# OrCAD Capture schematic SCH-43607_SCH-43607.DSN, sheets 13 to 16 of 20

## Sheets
13 P13_CPU SERDES & CLOCKS: size C
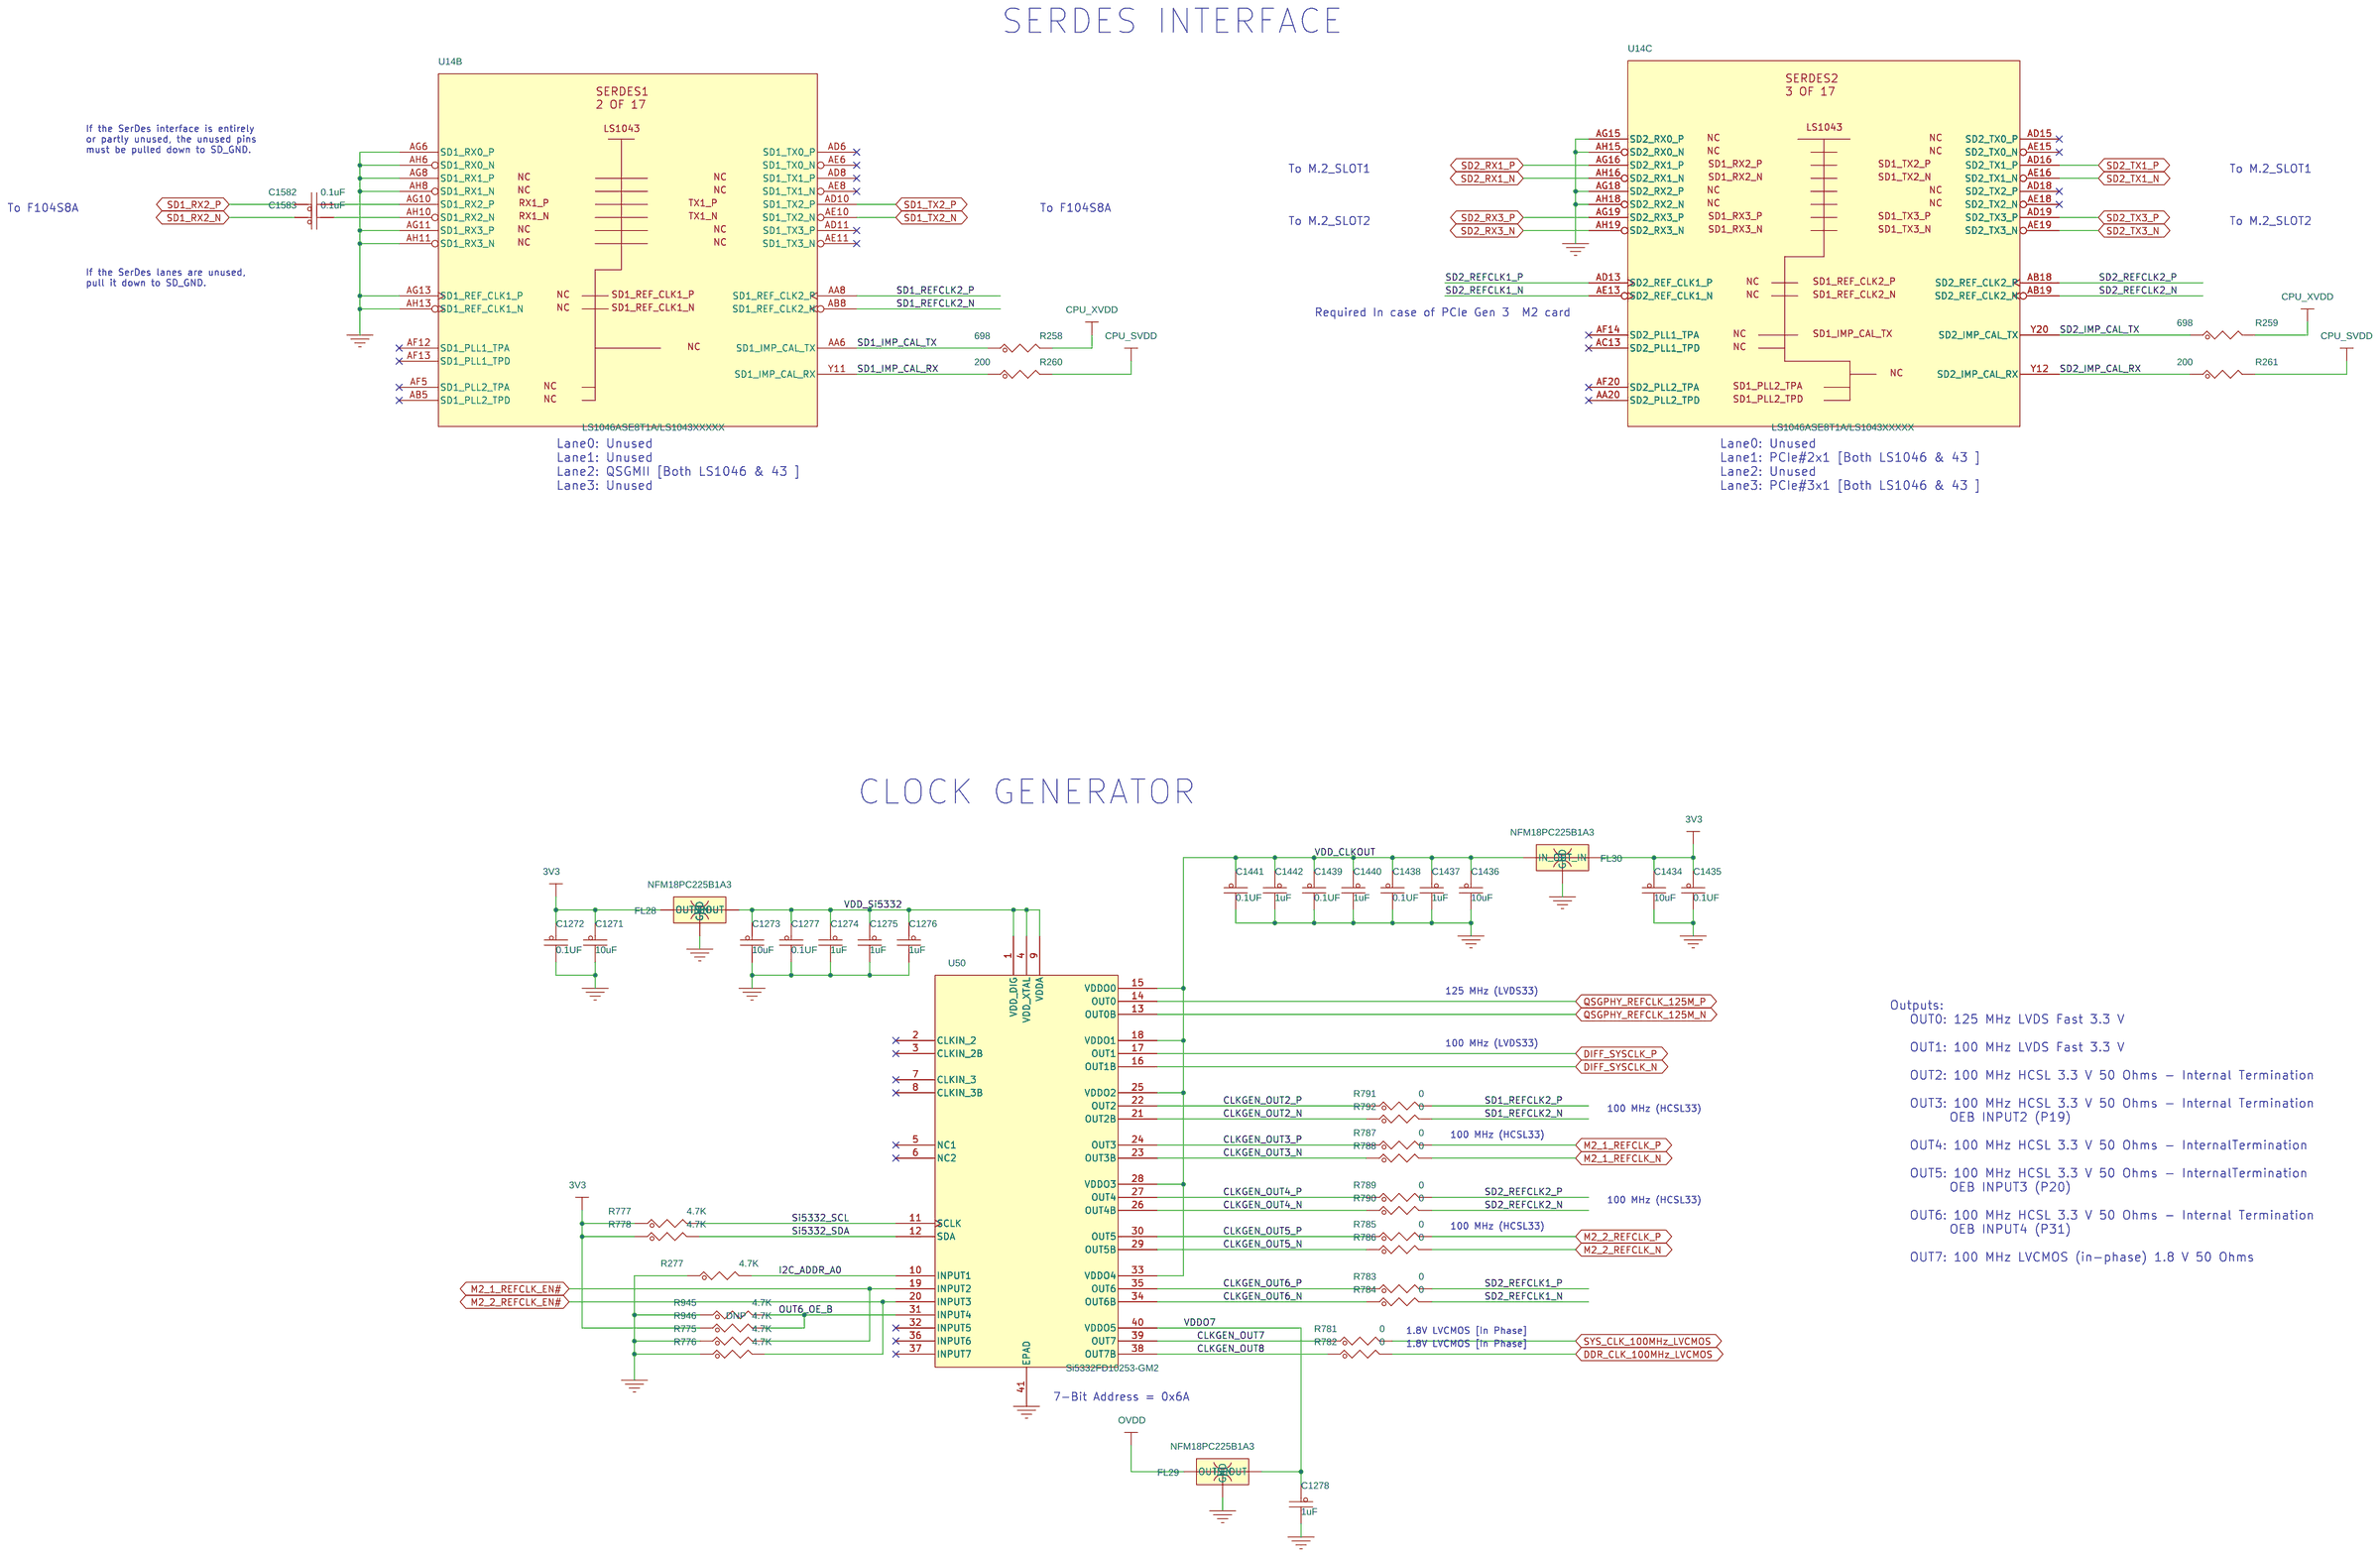
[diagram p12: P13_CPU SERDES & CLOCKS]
14 P14_M.2_PCIe_CARD: size C
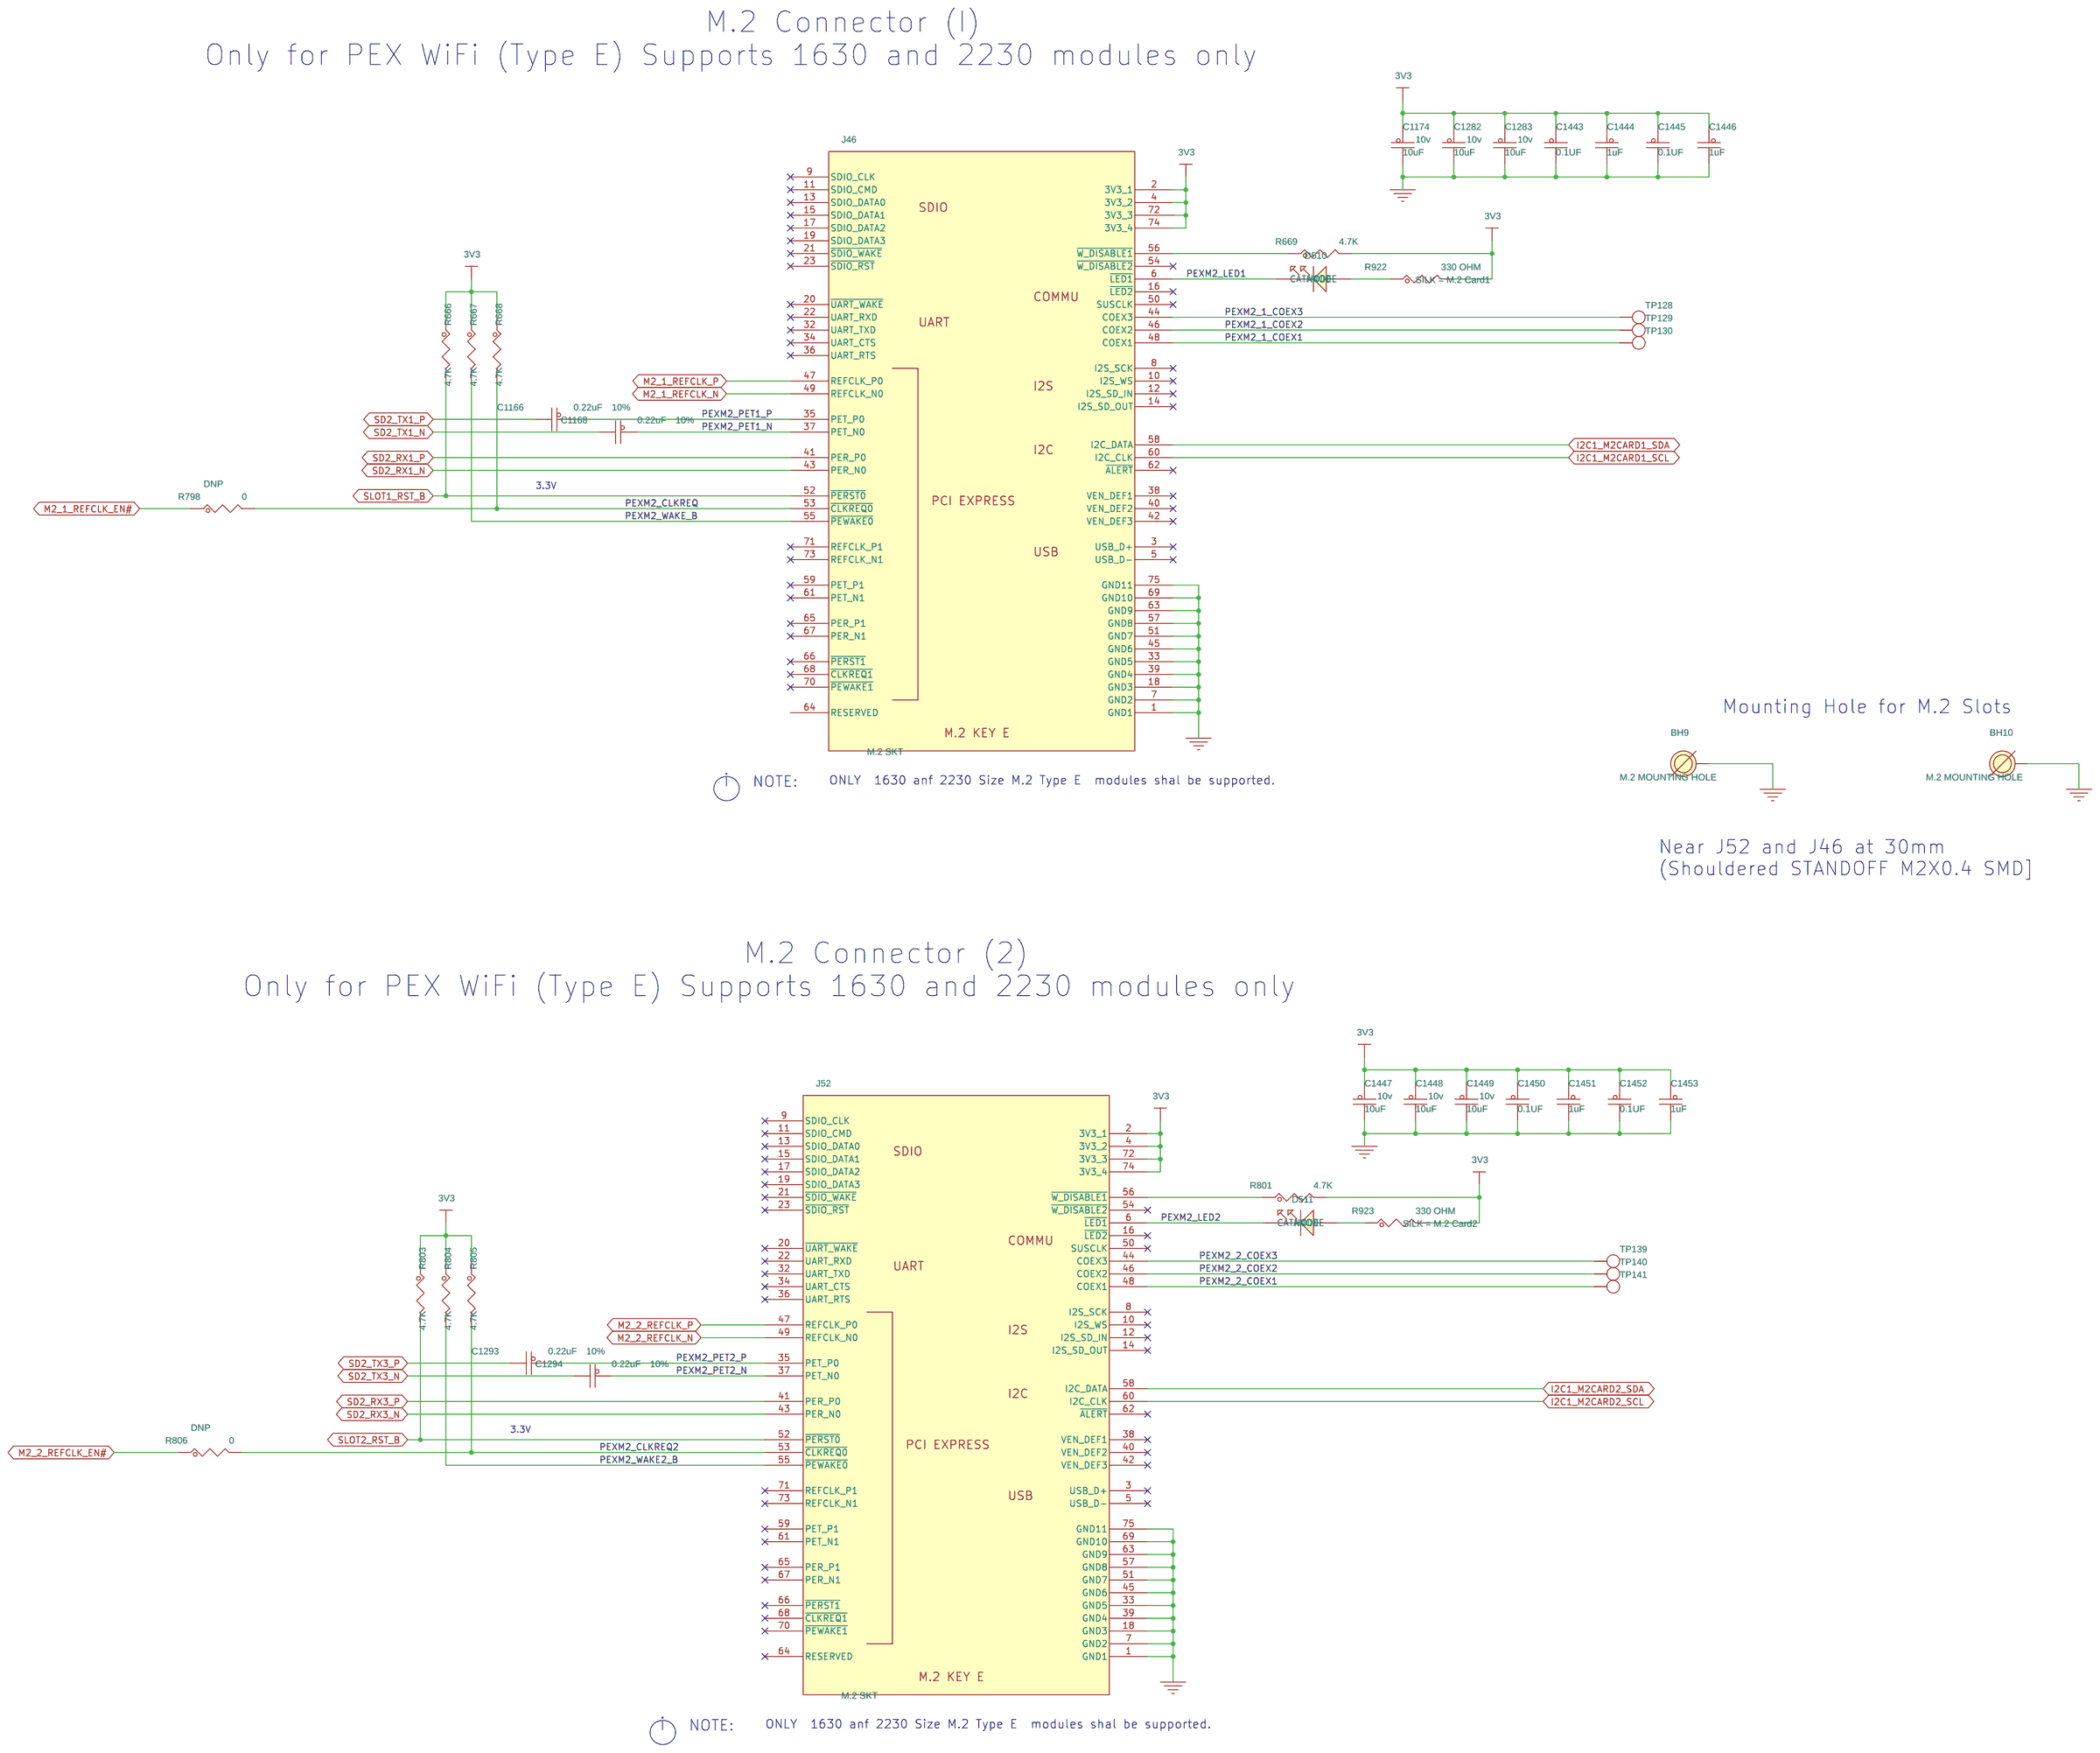
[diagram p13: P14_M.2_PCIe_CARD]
15 P15_QSGMII PHY (F104): size C
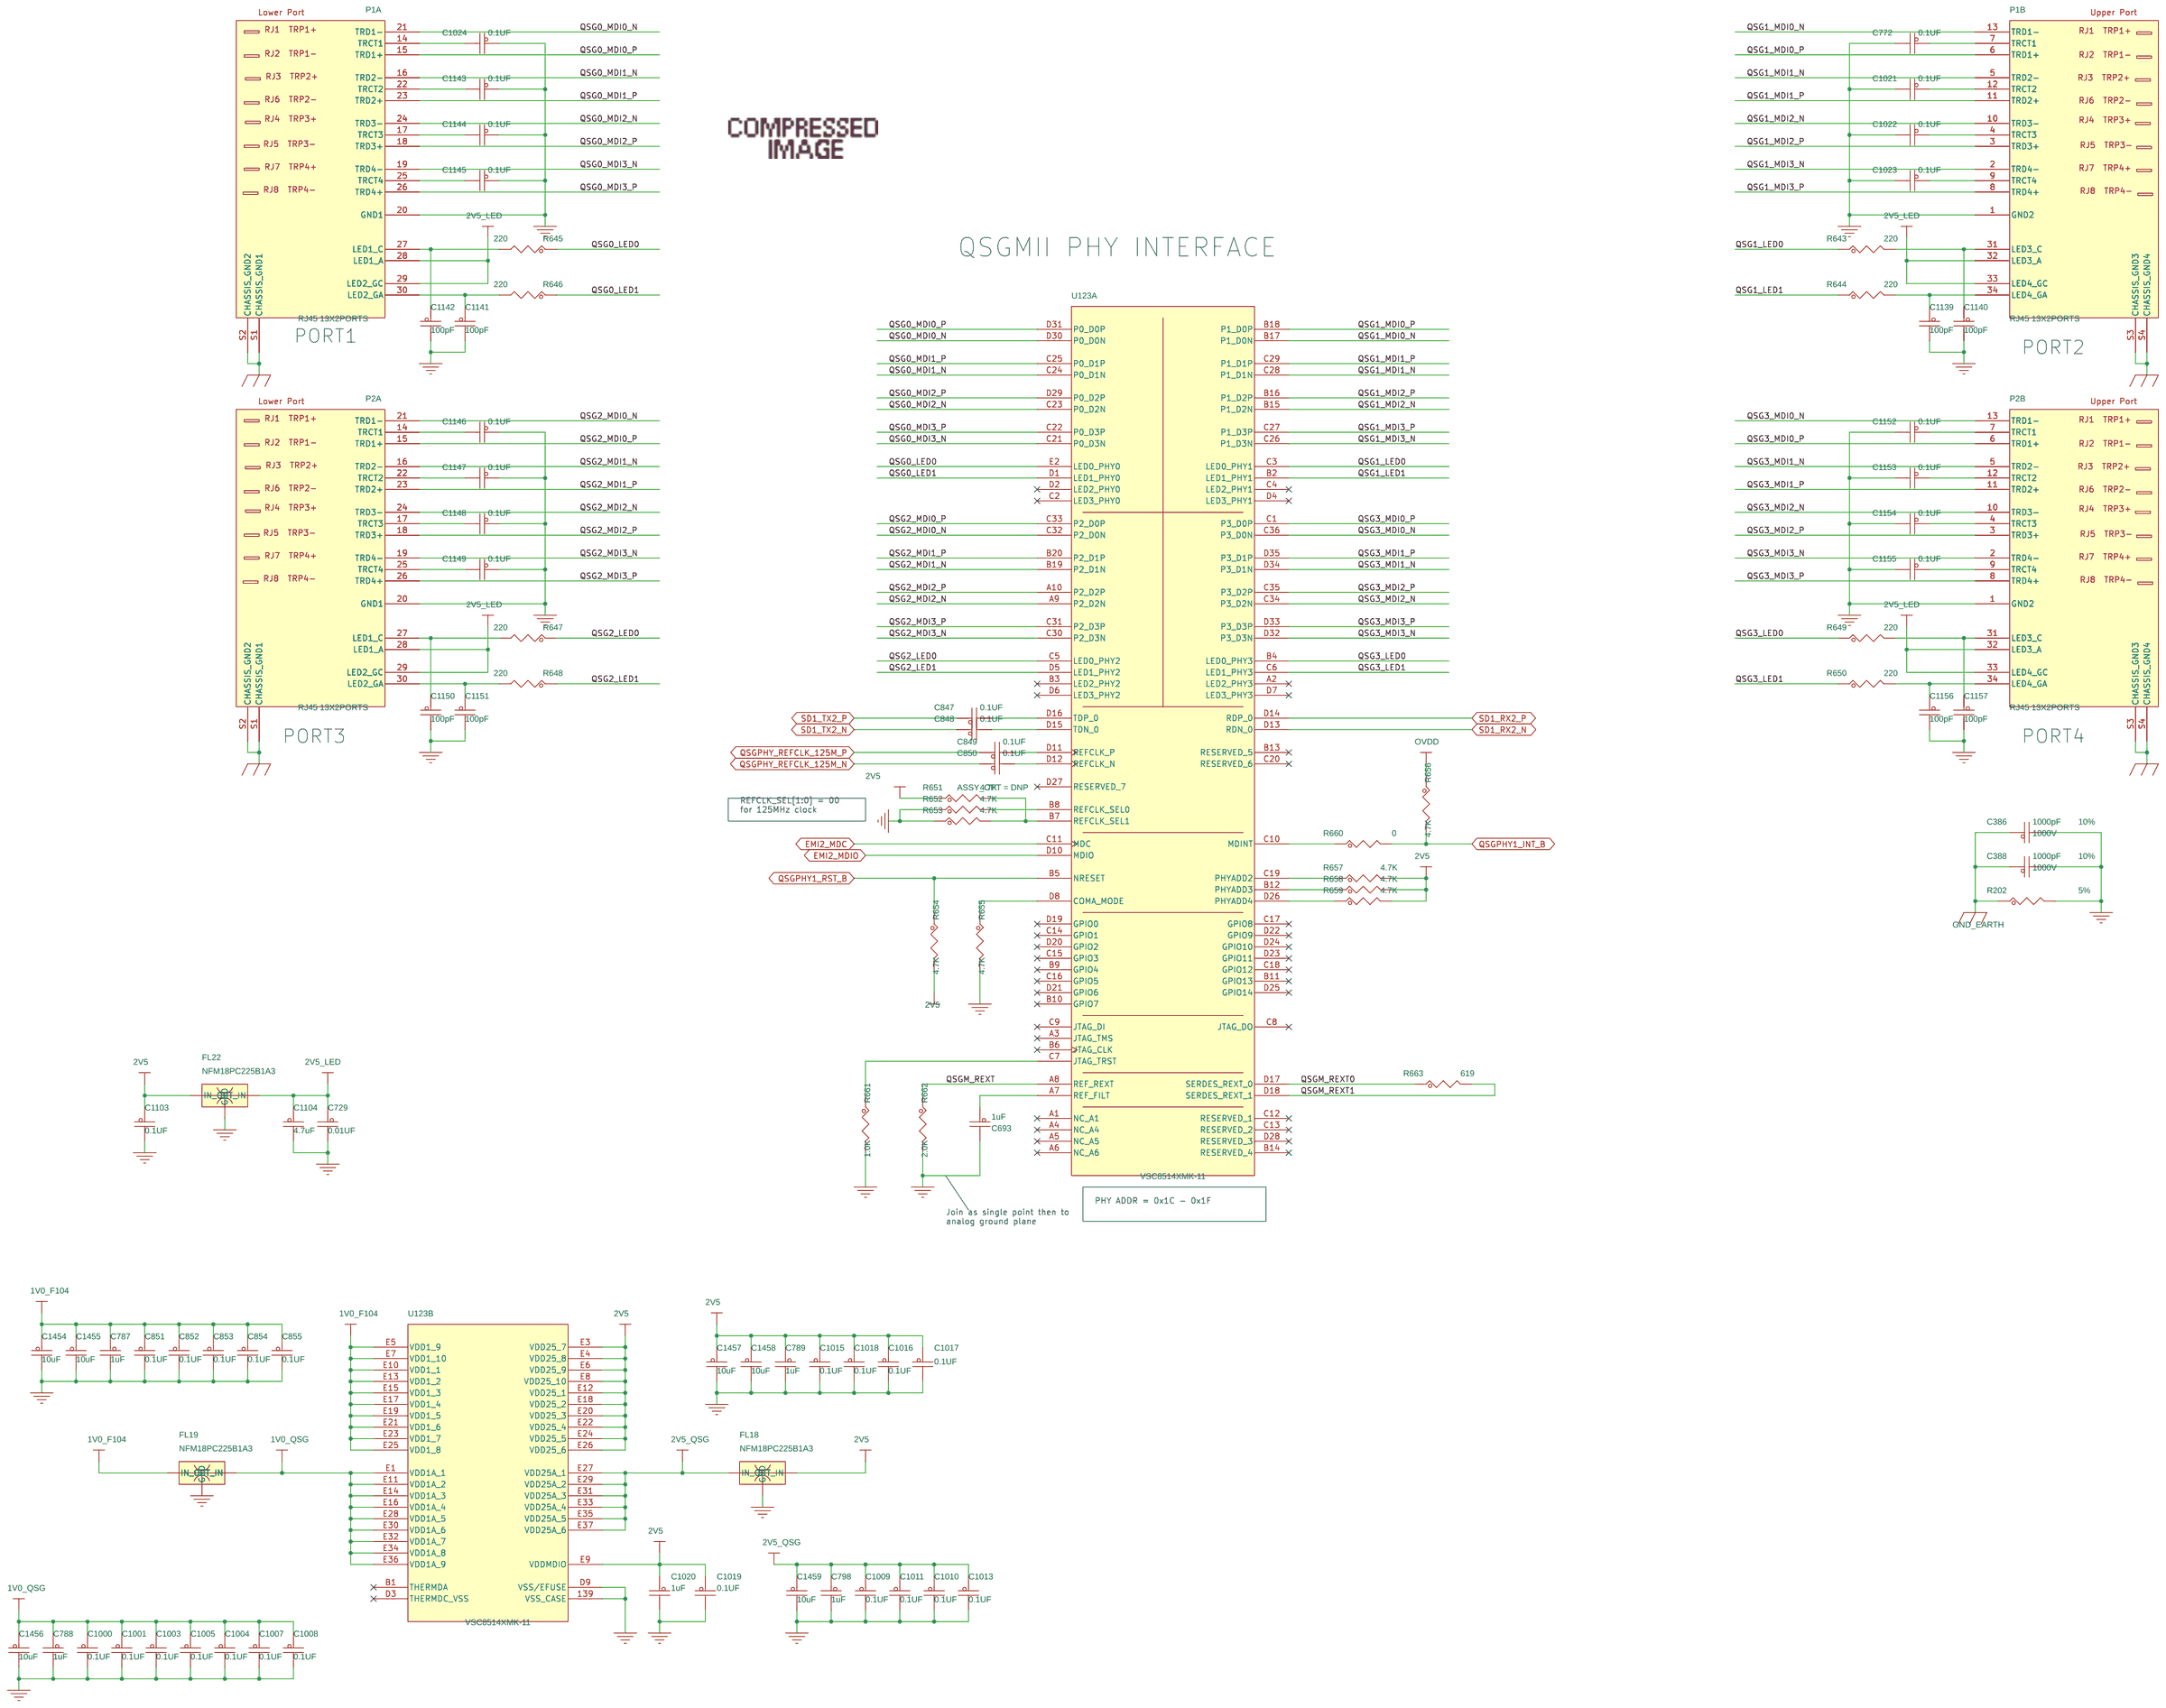
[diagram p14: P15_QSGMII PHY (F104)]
16 P16_I2C_INTERFACE: size C
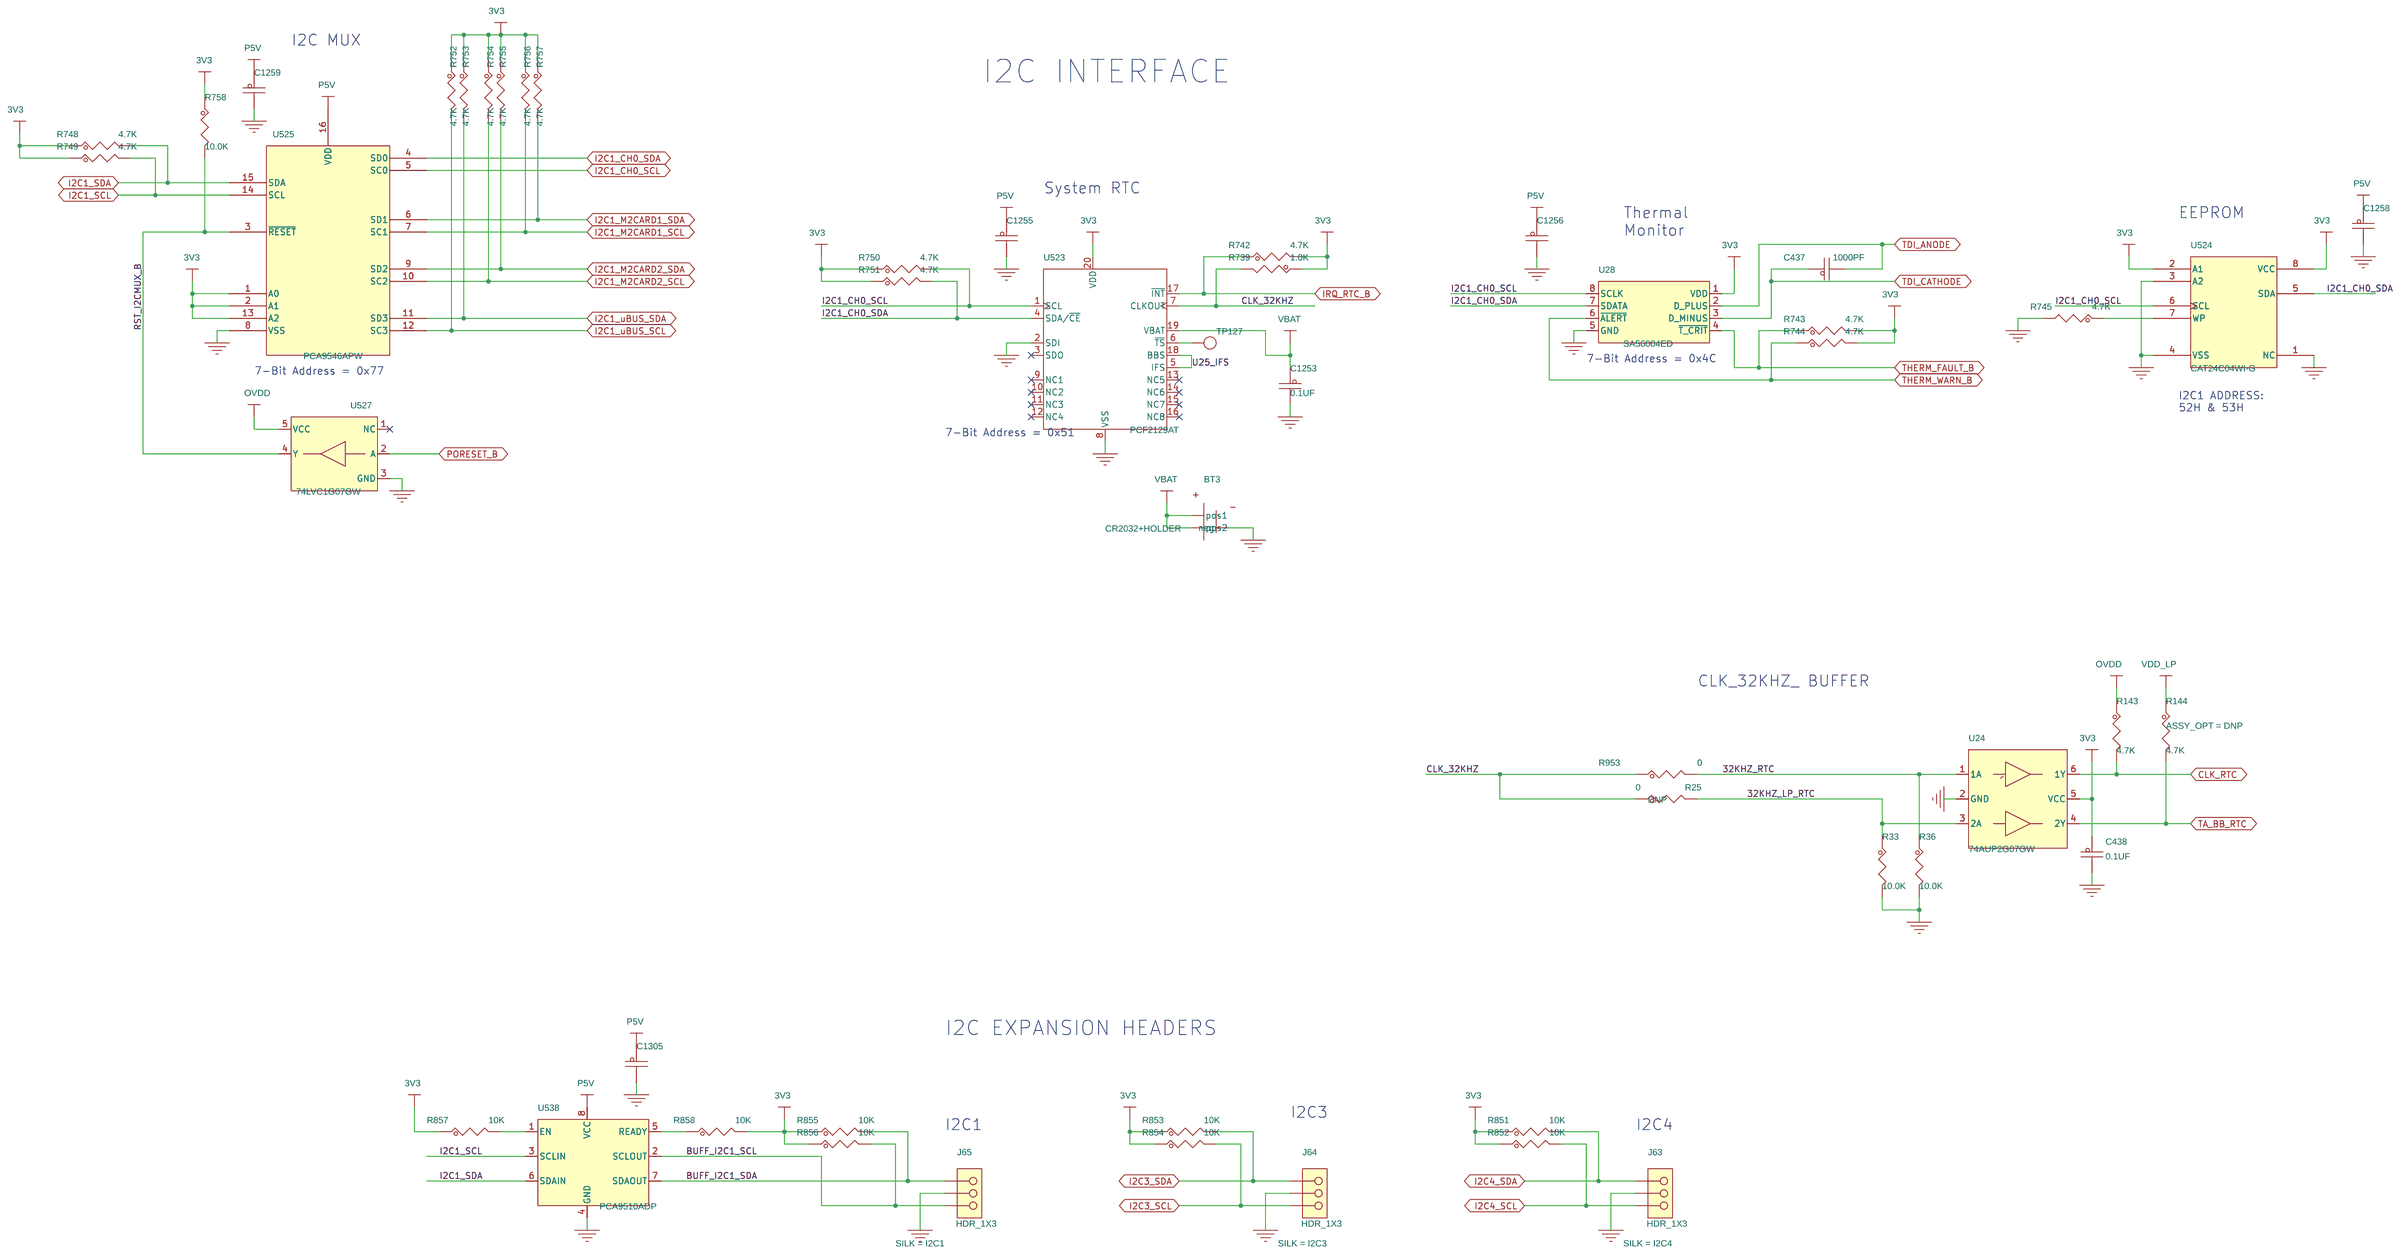
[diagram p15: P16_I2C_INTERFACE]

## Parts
sheet P13_CPU SERDES & CLOCKS
C1271  10uF  [CC0402_25]
C1272  0.1UF  [CC0402_25]
C1273  10uF  [CC0402_25]
C1274  1uF  [CC0402_25]
C1275  1uF  [CC0402_25]
C1276  1uF  [CC0402_25]
C1277  0.1UF  [CC0402_25]
C1278  1uF  [CC0402_25]
C1434  10uF  [CC0402_25]
C1435  0.1UF  [CC0402_25]
C1436  10uF  [CC0402_25]
C1437  1uF  [CC0402_25]
C1438  0.1UF  [CC0402_25]
C1439  0.1UF  [CC0402_25]
C1440  1uF  [CC0402_25]
C1441  0.1UF  [CC0402_25]
C1442  1uF  [CC0402_25]
C1582  0.1uF  [CC0201]
C1583  0.1uF  [CC0201]
FL28  NFM18PC225B1A3  [cc0603_nfm18pc]
FL29  NFM18PC225B1A3  [cc0603_nfm18pc]
FL30  NFM18PC225B1A3  [cc0603_nfm18pc]
R258  698  [RC0402_25]
R259  698  [RC0402_25]
R260  200  [RC0201]
R261  200  [RC0201]
R277  4.7K  [RC0402_25]
R775  4.7K  [RC0402_25]
R776  4.7K  [RC0402_25]
R777  4.7K  [RC0402_25]
R778  4.7K  [RC0402_25]
R781  0  [RC0402_25]
R782  0  [RC0402_25]
R783  0  [RC0402_25]
R784  0  [RC0402_25]
R785  0  [RC0402_25]
R786  0  [RC0402_25]
R787  0  [RC0402_25]
R788  0  [RC0402_25]
R789  0  [RC0402_25]
R790  0  [RC0402_25]
R791  0  [RC0402_25]
R792  0  [RC0402_25]
R945  4.7K  [RC0402_25]
R946  4.7K  [RC0402_25]
U50  Si5332FD10253-GM2  [qfn40_0p5_6x6_2p6ep]
sheet P14_M.2_PCIe_CARD
BH9  M.2 MOUNTING HOLE  [mh_c256-165t]
BH10  M.2 MOUNTING HOLE  [mh_c256-165t]
C1166  0.22uF  [CC0201]
C1168  0.22uF  [CC0201]
C1174  10uF  [CC0603_OV]
C1282  10uF  [CC0603_OV]
C1283  10uF  [CC0603_OV]
C1293  0.22uF  [CC0201]
C1294  0.22uF  [CC0201]
C1443  0.1UF  [CC0402_25]
C1444  1uF  [CC0402_25]
C1445  0.1UF  [CC0402_25]
C1446  1uF  [CC0402_25]
C1447  10uF  [CC0603_OV]
C1448  10uF  [CC0603_OV]
C1449  10uF  [CC0603_OV]
C1450  0.1UF  [CC0402_25]
C1451  1uF  [CC0402_25]
C1452  0.1UF  [CC0402_25]
C1453  1uF  [CC0402_25]
D510  LED_GREEN  [LED_0603]
D511  LED_GREEN  [LED_0603]
J46  M.2 SKT  [con_67_0p5_22x7p75_ra]
J52  M.2 SKT  [con_67_0p5_22x7p75_ra]
R666  4.7K  [RC0402_25]
R667  4.7K  [RC0402_25]
R668  4.7K  [RC0402_25]
R669  4.7K  [RC0402_25]
R798  0  [RC0402_25]
R801  4.7K  [RC0402_25]
R803  4.7K  [RC0402_25]
R804  4.7K  [RC0402_25]
R805  4.7K  [RC0402_25]
R806  0  [RC0402_25]
R922  330 OHM  [RC0402_25]
R923  330 OHM  [RC0402_25]
TP128  TP_PTH  [TP_PTH]
TP129  TP_PTH  [TP_PTH]
TP130  TP_PTH  [TP_PTH]
TP139  TP_PTH  [TP_PTH]
TP140  TP_PTH  [TP_PTH]
TP141  TP_PTH  [TP_PTH]
sheet P15_QSGMII PHY (F104)
C386  1000pF  [CC0805_OV]
C388  1000pF  [CC0805_OV]
C693  1uF  [CC0402_25]
C729  0.01UF  [CC0402_25]
C772  0.1UF  [CC0402_25]
C787  1uF  [CC0402_25]
C788  1uF  [CC0402_25]
C789  1uF  [CC0402_25]
C798  1uF  [CC0402_25]
C847  0.1UF  [CC0402_25]
C848  0.1UF  [CC0402_25]
C849  0.1UF  [CC0402_25]
C850  0.1UF  [CC0402_25]
C851  0.1UF  [CC0402_25]
C852  0.1UF  [CC0402_25]
C853  0.1UF  [CC0402_25]
C854  0.1UF  [CC0402_25]
C855  0.1UF  [CC0402_25]
C1000  0.1UF  [CC0402_25]
C1001  0.1UF  [CC0402_25]
C1003  0.1UF  [CC0402_25]
C1004  0.1UF  [CC0402_25]
C1005  0.1UF  [CC0402_25]
C1007  0.1UF  [CC0402_25]
C1008  0.1UF  [CC0402_25]
C1009  0.1UF  [CC0402_25]
C1010  0.1UF  [CC0402_25]
C1011  0.1UF  [CC0402_25]
C1013  0.1UF  [CC0402_25]
C1015  0.1UF  [CC0402_25]
C1016  0.1UF  [CC0402_25]
C1017  0.1UF  [CC0402_25]
C1018  0.1UF  [CC0402_25]
C1019  0.1UF  [CC0402_25]
C1020  1uF  [CC0402_25]
C1021  0.1UF  [CC0402_25]
C1022  0.1UF  [CC0402_25]
C1023  0.1UF  [CC0402_25]
C1024  0.1UF  [CC0402_25]
C1103  0.1UF  [CC0402_25]
C1104  4.7uF  [CC0805_OV]
C1139  100pF  [CC0402_25]
C1140  100pF  [CC0402_25]
C1141  100pF  [CC0402_25]
C1142  100pF  [CC0402_25]
C1143  0.1UF  [CC0402_25]
C1144  0.1UF  [CC0402_25]
C1145  0.1UF  [CC0402_25]
C1146  0.1UF  [CC0402_25]
C1147  0.1UF  [CC0402_25]
C1148  0.1UF  [CC0402_25]
C1149  0.1UF  [CC0402_25]
C1150  100pF  [CC0402_25]
C1151  100pF  [CC0402_25]
C1152  0.1UF  [CC0402_25]
C1153  0.1UF  [CC0402_25]
C1154  0.1UF  [CC0402_25]
C1155  0.1UF  [CC0402_25]
C1156  100pF  [CC0402_25]
C1157  100pF  [CC0402_25]
C1454  10uF  [CC0402_25]
C1455  10uF  [CC0402_25]
C1456  10uF  [CC0402_25]
C1457  10uF  [CC0402_25]
C1458  10uF  [CC0402_25]
C1459  10uF  [CC0402_25]
FL18  NFM18PC225B1A3  [cc0603_nfm18pc]
FL19  NFM18PC225B1A3  [cc0603_nfm18pc]
FL22  NFM18PC225B1A3  [cc0603_nfm18pc]
P1  RJ45 13X2PORTS  [con_rj45_2x1_th_ra]  (sections A,B)
P2  RJ45 13X2PORTS  [con_rj45_2x1_th_ra]  (sections A,B)
R202  1.0M  [RC1206_OV]
R643  220  [RC0402_25]
R644  220  [RC0402_25]
R645  220  [RC0402_25]
R646  220  [RC0402_25]
R647  220  [RC0402_25]
R648  220  [RC0402_25]
R649  220  [RC0402_25]
R650  220  [RC0402_25]
R651  4.7K  [RC0402_25]
R652  4.7K  [RC0402_25]
R653  4.7K  [RC0402_25]
R654  4.7K  [RC0402_25]
R655  4.7K  [RC0402_25]
R656  4.7K  [RC0402_25]
R657  4.7K  [RC0402_25]
R658  4.7K  [RC0402_25]
R659  4.7K  [RC0402_25]
R660  0  [RC0402_25]
R661  1.0K  [RC0402_25]
R662  2.0K  [RC0402_25]
R663  619  [RC0402_25]
U123  VSC8514_QFN  [AQFN138_0P65_12X12_EP]  (sections A,B)
sheet P16_I2C_INTERFACE
BT3  CR2032+HOLDER  [skt_bat_225x886_3V]
C437  1000PF  [CC0402_25]
C438  0.1UF  [CC0402_25]
C1253  0.1UF  [CC0402_25]
C1255  0.1UF  [CC0402_25]
C1256  0.1UF  [CC0402_25]
C1258  0.1UF  [CC0402_25]
C1259  0.1UF  [CC0402_25]
C1305  0.1UF  [CC0402_25]
J63  HDR_1X3  [HDR103]
J64  HDR_1X3  [HDR103]
J65  HDR_1X3  [HDR103]
R25  0  [RC0402_25]
R33  10.0K  [RC0402_25]
R36  10.0K  [RC0402_25]
R143  4.7K  [RC0402_25]
R144  4.7K  [RC0402_25]
R739  1.0K  [RC0402_25]
R742  4.7K  [RC0402_25]
R743  4.7K  [RC0402_25]
R744  4.7K  [RC0402_25]
R745  4.7K  [RC0402_25]
R748  4.7K  [RC0402_25]
R749  4.7K  [RC0402_25]
R750  4.7K  [RC0402_25]
R751  4.7K  [RC0402_25]
R752  4.7K  [RC0402_25]
R753  4.7K  [RC0402_25]
R754  4.7K  [RC0402_25]
R755  4.7K  [RC0402_25]
R756  4.7K  [RC0402_25]
R757  4.7K  [RC0402_25]
R758  10.0K  [RC0402_25]
R851  10K  [RC0402_25]
R852  10K  [RC0402_25]
R853  10K  [RC0402_25]
R854  10K  [RC0402_25]
R855  10K  [RC0402_25]
R856  10K  [RC0402_25]
R857  10K  [RC0402_25]
R858  10K  [RC0402_25]
R953  0  [RC0402_25]
TP127  TPAD_020  [tpad_020]
U24  74AUP2G07GW  [sot-363_0p65_smt]
U28  SA56004ED  [SO8_1P27_4X5]
U523  PCF2129AT  [so20_1p27_7p6x12p95]
U524  CAT24C04WI-G  [SO8_1P27_4X5]
U525  PCA9546APW  [TSSOP16]
U527  74LVC1G07GW  [sc70-5]
U538  PCA9510ADP  [tssop8_a]
sheet P20_SD_SPI_MIKRO_CLICK
U14  LS1046ASE8T1A/LS1043XXXXX  [BGA780_0P8_23X23MM]  (sections A,B,C,D,E,F,G,H,I,J,K,L,M,N,O,P,Q)

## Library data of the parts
C1271 C1273 C1434 C1436 C1454-C1459 = CAP_NP: CAP CER 10UF 6.3V 20% X6S 0402; AGILE_PN: 150-80079; CAD_APPROVED: Yes; FPLIST: CC0402_25,CC0402_HD,0402_CC; HEIGHT: 0.7MM; MFG_NAME01: MURATA; MFG_PN01: GRM155C80J106ME11D; ROHS: Yes; Temp_Range: -55 to 105&#8451;; Tolerance: 20%; VOLTAGE: 6.3V
C1272 C1277 C1435 C1438 C1439 C1441 = CAP_NP: CAP CER 0.1UF 25V 10% X5R 0402; AGILE_PN: 150-80045; CAD_APPROVED: Yes; FPLIST: CC0402_25,CC0402_HD,0402_CC; HEIGHT: 0.55MM; MFG_NAME01: Samsung Electro Mechanics; MFG_PN01: CL05A104KA5NNNC; ROHS: Yes; Tolerance: 10%; VOLTAGE: 25V
C693 C787-C789 C798 C1020 C1274-C1276 C1278 C1437 C1440 C1442 = CAP_NP: CAP CER 1uF 25V 10% X5R 0402; AGILE_PN: 150-80001; CAD_APPROVED: Yes; FPLIST: CC0402_25,CC0402_HD,0402_CC; HEIGHT: 0.55MM; MFG_NAME01: MURATA; MFG_PN01: GRM155R61E105KA12; PRIORITY_PN: 021-00191; ROHS: Yes; ROOM: RS232; SIGNAL_MODEL: DEFAULT_CAPACITOR_1e+06pF_2_1; TOL: 5%; Temp_Range: -55°C to +85°C; Tolerance: 10%; VOLTAGE: 25 V
C1582 C1583 = CAP_NP: CAP CER 0.1uF 16V 10% X5R 0201; AGILE_PN: 150-80059; CAD_APPROVED: Yes; FPLIST: CC0201,CC0201_HD,0201_CC; HEIGHT: 0.33MM; MFG_NAME01: MURATA; MFG_PN01: GRM033R61C104KE14D; ROHS: Yes; Temp_Range: -55 to +85°C; Tolerance: 10%; VOLTAGE: 16V
FL28-FL30 = NFM18PC225B1A3: CAP FILTER EMI 2.2uF 10V 20% -- 0603; AGILE_PN: 150-79428; CAD_APPROVED: Yes; HEIGHT: 0.9MM; MFG_NAME01: MURATA; MFG_PN01: NFM18PC225B1A3D; ROHS: Yes; ROOM: DUT_CLOSE; Temp_Range: -40 C to +85 C; Tolerance: 20%; VOLTAGE: 10V
R258 R259 = RES: RES MF 698 OHM 1/16W 1% 0402; AGILE_PN: 470-80981; CAD_APPROVED: Yes; FPLIST: RC0402_25,RC0402_HD,0402_CC; HEIGHT: 0.4MM; MFG_NAME01: YAGEO AMERICA; MFG_PN01: RC0402FR-07698RL; ROHS: Yes
R260 R261 = RES: RES SMD 200 OHM 1% 1/20W 0201; AGILE_PN: 470-82302; CAD_APPROVED: Yes; FPLIST: RC0201,0201_CC; HEIGHT: 0.28MM; MFG_NAME01: VISHAY INTERTECHNOLOGY; MFG_PN01: CRCW0201200RFKED; ROHS: Yes; Temp_Range: -55°C ~ 155°C; Tolerance: 1%
R143 R277 R652-R659 R666-R669 R742-R745 R748-R757 R775-R778 R801 R803-R805 R945 = RES: RES MF 4.70K 1/16W 1% 0402; AGILE_PN: 470-75418; CAD_APPROVED: Yes; FPLIST: RC0402_25,RC0402_HD,0402_CC; HEIGHT: 0.4mm; MFG_NAME01: WALSIN TECHNOLOGY CORP.; MFG_PN01: WR04X4701FTL; ROHS: Yes; Tolerance: 1%
R660 R781-R792 R953 = RES: RES MF ZERO OHM 1/10W -- 0402; AGILE_PN: 470-79965; CAD_APPROVED: Yes; FPLIST: RC0402_25,RC0402_HD,RC0402_X2,0402_CC; HEIGHT: 0.4MM; MFG_NAME01: Panasonic; MFG_PN01: ERJ-2GE0R00X; ROHS: Yes
R144 R651 R946 = RES: RES MF 4.70K 1/16W 1% 0402; AGILE_PN: 470-75418; ASSY_OPT: DNP; CAD_APPROVED: Yes; FPLIST: RC0402_25,RC0402_HD,0402_CC; HEIGHT: 0.4mm; MFG_NAME01: WALSIN TECHNOLOGY CORP.; MFG_PN01: WR04X4701FTL; ROHS: Yes; Tolerance: 1%
U50 = Si5332FD10253-GM2_QFN40: IC CLK GEN LOW JITTER 8 CLK-OUT 5-200MHz 1.8/2.5/3.3V QFN40; AGILE_PN: 312-82170; CAD_APPROVED: Yes; HEIGHT: 1.1MM; MFG_NAME01: SILICON LABORATORIES; ROHS: Yes; Temp_Range: -40 C TO -85 C
BH9 BH10 = MOUNT_HOLE: MOUNTING HOLE PLATED 165.36MIL DRILL/ 255.9 MIL PAD NO PART TO ORDER; AGILE_PN: 280-77181; CAD_APPROVED: Yes; HEIGHT: 0.127MM; MFG_NAME01: none; MFG_PN01: none; ROHS: Yes
C1166 C1168 C1293 C1294 = CAP_NP: CAP CER 0.22uF 6.3V 10% X5R 0201; AGILE_PN: 150-79474; CAD_APPROVED: Yes; FPLIST: CC0201,CC0201_HD,0201_CC,cc_0201_cir; HEIGHT: 0.33MM; MFG_NAME01: MURATA; MFG_PN01: GRM033R60J224KE15D; ROHS: Yes; Tolerance: 10%; VOLTAGE: 6.3V
C1174 C1282 C1283 C1447-C1449 = CAP_NP: CAP CER 10UF 10V 10% X5R 0603; AGILE_PN: 150-78675; CAD_APPROVED: Yes; FPLIST: CC0603_OV,CC0603,0603_CC; HEIGHT: 1.016MM; MFG_NAME01: MURATA; MFG_PN01: GRM188R61A106KE69D; PRIORITY_PN: 021-00358; ROHS: Yes; ROOM: SDHC; SIGNAL_MODEL: DEFAULT_CAPACITOR_1e+07pF_2_1; TOL: 10%; Temp_Range: -55°C ~ 85°C; Tolerance: 10%; VOLTAGE: 10v
C438 C851-C855 C1000 C1001 C1003-C1005 C1007-C1011 C1013 C1015-C1019 C1103 C1443 C1445 C1450 C1452 = CAP_NP: CAP CER 0.1UF 25V 10% X5R 0402; AGILE_PN: 150-80045; CAD_APPROVED: Yes; FPLIST: CC0402_25,CC0402_HD,0402_CC; HEIGHT: 0.55MM; MFG_NAME01: Samsung Electro Mechanics; MFG_PN01: CL05A104KA5NNNC; ROHS: Yes; TOL: 10%; Tolerance: 10%; VOLTAGE: 25V
C1444 C1446 C1451 C1453 = CAP_NP: CAP CER 1uF 25V 10% X5R 0402; AGILE_PN: 150-80001; CAD_APPROVED: Yes; FPLIST: CC0402_25,CC0402_HD,0402_CC; HEIGHT: 0.55MM; MFG_NAME01: MURATA; MFG_PN01: GRM155R61E105KA12; ROHS: Yes; SIGNAL_MODEL: DEFAULT_CAPACITOR_1e+06pF_2_1; TOL: 10%; Temp_Range: -55°C to +85°C; Tolerance: 10%; VOLTAGE: 25 V; WVDC: 10V
D510 = LED: LED ULTRA-BRIGHT GREEN SMT 0603; AGILE_PN: 370-75077; CAD_APPROVED: YES; HEIGHT: 0.8MM; MFG_NAME01: LITE ON; MFG_PN01: LTST-C190KGKT; ROHS: Yes; SILK: M.2 Card1
D511 = LED: LED ULTRA-BRIGHT GREEN SMT 0603; AGILE_PN: 370-75077; CAD_APPROVED: YES; HEIGHT: 0.8MM; MFG_NAME01: LITE ON; MFG_PN01: LTST-C190KGKT; ROHS: Yes; SILK: M.2 Card2
J46 J52 = CON_67_FEMALE_RA: CON 67 PCI EXPRESS M.2 CRD KEY- E SKT RA SMT 0.5MM SP 165H AU; AGILE_PN: TMP-WF-32260; CAD_APPROVED: Yes; HEIGHT: 4.2MM; MFG_NAME01: ANYTRONIC CORPORATION LIMITED; MFG_PN01: 1J0E 42010R-2LF; PRE_APN: 211-80281; ROHS: Yes; Temp_Range: -55C to +105C
R25 R798 R806 = RES: RES MF ZERO OHM 1/10W -- 0402; AGILE_PN: 470-79965; ASSY_OPT: DNP; CAD_APPROVED: Yes; FPLIST: RC0402_25,RC0402_HD,RC0402_X2,0402_CC; HEIGHT: 0.4MM; MFG_NAME01: Panasonic; MFG_PN01: ERJ-2GE0R00X; ROHS: Yes
R922 R923 = RES: RES MF 330 OHM 1/16W 1% 0402; AGILE_PN: 470-80566; CAD_APPROVED: Yes; FPLIST: RC0402_25,RC0402_HD,0402_CC; HEIGHT: 0.4MM; MFG_NAME01: WALSIN TECHNOLOGY CORP.; MFG_PN01: WR04X3300FTL; ROHS: Yes; Tolerance: 1%
TP128-TP130 TP139-TP141 = TestLoop: TEST POINT PAD 035-018MIL TH, NO PART TO ORDER; AGILE_PN: 210-77612; CAD_APPROVED: Yes; HEIGHT: 0.1 mm; MFG_NAME01: NOTACOMPONENT; MFG_PN01: NOTACOMPONENT; ROHS: Yes
C386 C388 = CAP_NP: CAP CER 1000pF 1000V 10% X7R 0805; AGILE_PN: 150-78841; CAD_APPROVED: Yes; FPLIST: CC0805_OV,CC0805,0805_CC; HEIGHT: 1.4MM; MFG_NAME01: Kemet; MFG_PN01: C0805C102KDRACTU; ROHS: Yes; Tolerance: 10%; VOLTAGE: 1000V
C729 = CAP_NP: CAP CER 0.01UF 50V 10% X7R 0402; AGILE_PN: 150-30114; CAD_APPROVED: Yes; FPLIST: CC0402_25,CC0402_HD,0402_CC; HEIGHT: 0.74 MM; MFG_NAME01: WALSIN TECHNOLOGY CORP.; MFG_PN01: 0402B103K500CT; PRIORITY_PN: 021-00302; ROHS: Yes; ROOM: PEX_SLOTS123_REFCLK; SIGNAL_MODEL: DEFAULT_CAPACITOR_10000pF_2_1; TOL: 10%; Tolerance: 10%; VOLTAGE: 50V
C772 C1021-C1024 C1143-C1149 C1152-C1155 = CAP_NP: CAP CER 0.1UF 25V 10% X5R 0402; AGILE_PN: 150-80045; CAD_APPROVED: Yes; FPLIST: CC0402_25,CC0402_HD,0402_CC; HEIGHT: 0.55MM; MFG_NAME01: Samsung Electro Mechanics; MFG_PN01: CL05A104KA5NNNC; PRIORITY_PN: 021-00389; ROHS: Yes; ROOM: PEX_SLOTS123_REFCLK; SIGNAL_MODEL: DEFAULT_CAPACITOR_100000pF_2_1; TOL: 10%; Tolerance: 10%; VOLTAGE: 25V
C847-C850 = CAP_NP: CAP CER 0.1UF 25V 10% X5R 0402; AGILE_PN: 150-80045; CAD_APPROVED: Yes; FPLIST: CC0402_25,CC0402_HD,0402_CC; HEIGHT: 0.55MM; MFG_NAME01: Samsung Electro Mechanics; MFG_PN01: CL05A104KA5NNNC; ROHS: Yes; SIGNAL_MODEL: CAP_NP_CC0201_DISCRETE_0.33MM_1_0.1UF; TOL: 10%; Tolerance: 10%; VOLTAGE: 25V
C1104 = CAP_NP: CAP CER 4.7UF 25V 10% X7R 0805; AGILE_PN: 150-75837; CAD_APPROVED: Yes; FPLIST: CC0805_OV,CC0805,0805_CC; HEIGHT: 1.4MM; MFG_NAME01: CAPAX TECHNOLOGIES INC.; MFG_PN01: 0805X475K250SNT; PRIORITY_PN: 921-00228; ROHS: Yes; ROOM: PS_DDR1_2_VTT; Tolerance: 10%; VOLTAGE: 25V
C1139-C1142 C1150 C1151 C1156 C1157 = CAP_NP: CAP CER 100PF 50V 5% X7R 0402; AGILE_PN: 150-78133; CAD_APPROVED: Yes; FPLIST: CC0402_25,CC0402_HD,0402_CC; HEIGHT: 0.6MM; MFG_NAME01: CAL-CHIP; MFG_PN01: GMC04X7R101J50NT-LF; ROHS: Yes; TOL: 5%; Tolerance: 5%
FL18 FL19 FL22 = NFM18PC225B1A3: CAP FILTER EMI 2.2uF 10V 20% -- 0603; AGILE_PN: 150-79428; CAD_APPROVED: Yes; HEIGHT: 0.9MM; MFG_NAME01: MURATA; MFG_PN01: NFM18PC225B1A3D; ROHS: Yes; Temp_Range: -40 C to +85 C; Tolerance: 20%; VOLTAGE: 10V
P1 P2 = RJ45_MAG_2X1_LED: CON 13 RJ-45 DUAL SKT SHLD RA TH G/YG LEDS 2MM SP 1069H AU --; AGILE_PN: 210-81945; CAD_APPROVED: Yes; HEIGHT: 27.15MM; MFG_NAME01: LINK-PP; MFG_PN01: LPJG17102A96NL; ROHS: Yes
R202 = RES: RES MF 1.0M 1/4W 5% 1206; AGILE_PN: 470-75658; CAD_APPROVED: Yes; FPLIST: RC1206_OV,RC1206,1206_CC; HEIGHT: 0.75MM; MFG_NAME01: BOURNS; MFG_PN01: CR1206JW105ELF; ROHS: Yes; Tolerance: 5%
R643-R650 = RES: RES MF 220 OHM 1/16W 5% 0402; AGILE_PN: 470-75607; CAD_APPROVED: Yes; FPLIST: RC0402_25,RC0402_HD,0402_CC; HEIGHT: 0.45mm; MFG_NAME01: NIC COMPONENTS CORP; MFG_PN01: NRCL04J221TRF; ROHS: Yes; Tolerance: 5%
R661 R739 = RES: RES MF 1.0K 1/16W 1% 0402; AGILE_PN: 470-76037; CAD_APPROVED: Yes; FPLIST: RC0402_25,RC0402_HD,RC0402_X2,0402_CC; HEIGHT: 0.4MM; MFG_NAME01: YAGEO AMERICA; MFG_PN01: RC0402FR-071KL; ROHS: Yes; Tolerance: 1%
R662 = RES: RES MF 2.0K 1/16W 1% 0402; AGILE_PN: 470-75356; CAD_APPROVED: Yes; FPLIST: RC0402_25,RC0402_HD,0402_CC; HEIGHT: 0.4mm; MFG_NAME01: BOURNS; MFG_PN01: CR0402-FX-2001GLF; ROHS: Yes; Tolerance: 1%
R663 = RES: RES MF 619 OHM 1/16W 1% 0402; AGILE_PN: 470-80833; CAD_APPROVED: Yes; FPLIST: RC0402_25,RC0402_HD,0402_CC; HEIGHT: 0.4MM; MFG_NAME01: WALSIN TECHNOLOGY CORP.; MFG_PN01: WR04X6190FTL; ROHS: Yes; Tolerance: 1%
U123 = VSC8514_QFN_138P_A: IC SGMII ETHERNET PHY QFN 138; AGILE_PN: 312-80946; CAD_APPROVED: Yes; HEIGHT: 2.06 MM; MFG_NAME01: MICROCHIP TECHNOLOGY INC; MFG_PN01: VSC8514XMK-11; ROHS: Yes
BT3 = BATTERY_SKT_3V: SUBASSEMBLY  BATTERY HOLDER CR2032 3V TH W/ BATTERY LITHIUM 3V 220MAH; AGILE_PN: 750-77403; CAD_APPROVED: Yes; HEIGHT: 23.28MM; MFG_NAME01: SUBASSEMBLY; MFG_PN01: 670-00012,801-75534; ROHS: Yes
C437 = CAP_NP: CAP CER 1000PF 50V 5% C0G 0402; AGILE_PN: 150-75591; CAD_APPROVED: Yes; FPLIST: CC0402_25,CC0402_HD,0402_CC; HEIGHT: 0.635MM; MFG_NAME01: VENKEL COMPANY; MFG_PN01: C0402C0G500-102JNP; ROHS: Yes
C1253 C1255 C1256 C1258 C1259 C1305 = CAP_NP: CAP CER 0.1UF 25V 10% X5R 0402; AGILE_PN: 150-80045; CAD_APPROVED: Yes; FPLIST: CC0402_25,CC0402_HD,0402_CC; HEIGHT: 0.55MM; MFG_NAME01: Samsung Electro Mechanics; MFG_PN01: CL05A104KA5NNNC; ROHS: Yes; SIGNAL_MODEL: DEFAULT_CAPACITOR_100000pF_2_1; TOL: 10%; Tolerance: 10%; VOLTAGE: 25V
J63 = CONN_HDR_3X1: HDR 1X3 TH 100MIL SP 338H AU 98L; AGILE_PN: 210-81491; CAD_APPROVED: Yes; HEIGHT: 8.59MM; MFG_NAME01: ANYTRONIC CORPORATION LIMITED; MFG_PN01: 0901S0203011N9T-31RF; ROHS: Yes; SILK: I2C4; Temp_Range: -55°C to +105°C
J64 = CONN_HDR_3X1: HDR 1X3 TH 100MIL SP 338H AU 98L; AGILE_PN: 210-81491; CAD_APPROVED: Yes; HEIGHT: 8.59MM; MFG_NAME01: ANYTRONIC CORPORATION LIMITED; MFG_PN01: 0901S0203011N9T-31RF; ROHS: Yes; SILK: I2C3; Temp_Range: -55°C to +105°C
J65 = CONN_HDR_3X1: HDR 1X3 TH 100MIL SP 338H AU 98L; AGILE_PN: 210-81491; CAD_APPROVED: Yes; HEIGHT: 8.59MM; MFG_NAME01: ANYTRONIC CORPORATION LIMITED; MFG_PN01: 0901S0203011N9T-31RF; ROHS: Yes; SILK: I2C1; Temp_Range: -55°C to +105°C
R33 R36 R758 = RES: RES MF 10.0K 1/16W 1% 0402; AGILE_PN: 470-80574; CAD_APPROVED: Yes; FPLIST: RC0402_25,RC0402_HD,0402_CC; HEIGHT: 0.4MM; MFG_NAME01: WALSIN TECHNOLOGY CORP.; MFG_PN01: WR04X1002FTL; ROHS: Yes; Tolerance: 1%
R851-R858 = RES: RES MF 10K 1/5W 1% AEC-Q200 0402; AGILE_PN: 470-80881; CAD_APPROVED: Yes; FPLIST: RC0402_25,RC0402_HD,0402_CC; HEIGHT: 0.4MM; MFG_NAME01: VISHAY INTERTECHNOLOGY; MFG_PN01: CRCW040210K0FKEDHP; ROHS: Yes; Temp_Range: -55&#8451; to 155&#8451;; Tolerance: 1%
TP127 = TestLoop: TEST POINT PAD 0.5MM DIA SMT, NO PART TO ORDER; AGILE_PN: 211-77484; CAD_APPROVED: Yes; HEIGHT: 0.1MM; ROHS: Yes
U24 = 74AUP2G07GW: IC BUFFER DUAL W/OPEN DRAIN OUT 0.8-3.6V SOT363; AGILE_PN: 312-81240; CAD_APPROVED: Yes; HEIGHT: 1.1MM; MFG_NAME01: NEXPERIA; MFG_PN01: 74AUP2G07GW,125; ROHS: Yes
U28 = SA56004ED_SO8: IC SMBUS REMOTE/LOCAL DIG TEMP SENSOR OVER TEMP ALARM 3-3.6V SO8; AGILE_PN: 312-81421; CAD_APPROVED: Yes; HEIGHT: 1.75 MM; MFG_NAME01: NXP SEMICONDUCTORS; MFG_PN01: SA56004ED,118; ROHS: Yes
U523 = PCF2129AT_SO_20P: IC RTC W/XTAL 1.8-4.2V SO20; AGILE_PN: 312-81231; CAD_APPROVED: Yes; HEIGHT: 2.65MM; MFG_NAME01: NXP SEMICONDUCTORS; MFG_PN01: PCF2129AT/2,518; ROHS: Yes; ROOM: I2C1_CH3
U524 = CAT24C04_SO8: IC MEM EEPROM SERIAL I2C 4Kb 1.7-5.5V SOIC8; AGILE_PN: 334-77384; CAD_APPROVED: Yes; HEIGHT: 1.75MM; MFG_NAME01: ON SEMICONDUCTOR; ROHS: Yes
U525 = PCA9546_16P: IC 4CH I2C-BUS SWITCH RESET 2.3V-5.5V TSSOP16; AGILE_PN: 312-81401; CAD_APPROVED: Yes; HEIGHT: 1.1 MM; MFG_NAME01: NXP SEMICONDUCTORS; MFG_PN01: PCA9546APW,118; ROHS: Yes
U527 = 74AUP1G07GW: IC BUF NON-INV SGL 1.65-5.5V TSSOP5; AGILE_PN: 312-81328; CAD_APPROVED: Yes; HEIGHT: 1.1 MM; MFG_NAME01: NEXPERIA; MFG_PN01: 74LVC1G07GW,125; ROHS: Yes
U538 = PCA9510ADP_8P: IC HOT SWAP I2C BUF 400KHZ 2.7-5.5V TSSOP8; AGILE_PN: 312-81129; CAD_APPROVED: Yes; HEIGHT: 1.1MM; MFG_NAME01: NXP SEMICONDUCTORS; ROHS: Yes
U14 = LS1043_1046_SS: IC MCU LS1046 and LS1043 FBGA780; AGILE_PN: TMP-WF-33894; CAD_APPROVED: Yes; HEIGHT: 2.61/2.07MM; MFG_NAME01: NXP SEMICONDUCTORS; PRE_APN: 344-02328; ROHS: Yes

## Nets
1V0_F104: C787.1 C851.1 C852.1 C853.1 C854.1 C855.1 C1454.1 C1455.1 FL19.1(IN_OUT) U123.E5(VDD1_9) U123.E7(VDD1_10) U123.E10(VDD1_1) U123.E13(VDD1_2) U123.E15(VDD1_3) U123.E17(VDD1_4) U123.E19(VDD1_5) U123.E21(VDD1_6) U123.E23(VDD1_7) U123.E25(VDD1_8) ; also on sheet 6
1V0_QSG: C788.1 C1000.1 C1001.1 C1003.1 C1004.1 C1005.1 C1007.1 C1008.1 C1456.1 FL19.3(OUT_IN) U123.E1(VDD1A_1) U123.E11(VDD1A_2) U123.E14(VDD1A_3) U123.E16(VDD1A_4) U123.E28(VDD1A_5) U123.E30(VDD1A_6) U123.E32(VDD1A_7) U123.E34(VDD1A_8) U123.E36(VDD1A_9)
2V5: C789.1 C1015.1 C1016.1 C1017.1 C1018.1 C1019.1 C1020.1 C1103.1 C1457.1 C1458.1 FL18.3(OUT_IN) FL22.1(IN_OUT) R651.1 R654.2 R657.2 R658.2 R659.2 U123.E3(VDD25_7) U123.E4(VDD25_8) U123.E6(VDD25_9) U123.E8(VDD25_10) U123.E9(VDDMDIO) U123.E12(VDD25_1) U123.E18(VDD25_2) U123.E20(VDD25_3) U123.E22(VDD25_4) U123.E24(VDD25_5) U123.E26(VDD25_6) ; also on sheet 6 8 10 11 18
2V5_LED: C729.1 C1104.1 FL22.3(OUT_IN) P1.28(LED1_A) P1.29(LED2_GC) P1.32(LED3_A) P1.33(LED4_GC) P2.28(LED1_A) P2.29(LED2_GC) P2.32(LED3_A) P2.33(LED4_GC)
2V5_QSG: C798.1 C1009.1 C1010.1 C1011.1 C1013.1 C1459.1 FL18.1(IN_OUT) U123.E27(VDD25A_1) U123.E29(VDD25A_2) U123.E31(VDD25A_3) U123.E33(VDD25A_4) U123.E35(VDD25A_5) U123.E37(VDD25A_6)
3V3: C438.1 C1174.1 C1255.1 C1256.1 C1258.1 C1259.1 C1271.1 C1272.1 C1282.1 C1283.1 C1305.1 C1434.1 C1435.1 C1443.1 C1444.1 C1445.1 C1446.1 C1447.1 C1448.1 C1449.1 C1450.1 C1451.1 C1452.1 C1453.1 FL28.3(OUT_IN) FL30.3(OUT_IN) J46.2(3V3_1) J46.4(3V3_2) J46.72(3V3_3) J46.74(3V3_4) J52.2(3V3_1) J52.4(3V3_2) J52.72(3V3_3) J52.74(3V3_4) R666.1 R667.1 R668.1 R669.2 R739.1 R742.2 R743.2 R744.2 R748.1 R749.1 R750.1 R751.1 R752.1 R753.1 R754.1 R755.1 R756.1 R757.1 R758.1 R777.1 R778.1 R801.2 R803.1 R804.1 R805.1 R851.1 R852.1 R853.1 R854.1 R855.1 R856.1 R857.1 R858.2 R922.2 R923.2 R946.1 U24.5(VCC) U28.1(VDD) U523.20(VDD) U524.2(A1) U524.8(VCC) U525.1(A0) U525.2(A1) U525.13(A2) U525.16(VDD) U538.8(VCC) ; also on sheet 5 6 7 8 9 17 18 19 20
GND: BH9.1 BH10.1 BT3.3(neg) C386.2 C388.2 C438.2 C693.2 C729.2 C772.2 C787.2 C788.2 C789.2 C798.2 C851.2 C852.2 C853.2 C854.2 C855.2 C1000.2 C1001.2 C1003.2 C1004.2 C1005.2 C1007.2 C1008.2 C1009.2 C1010.2 C1011.2 C1013.2 C1015.2 C1016.2 C1017.2 C1018.2 C1019.2 C1020.2 C1021.2 C1022.2 C1023.2 C1024.1 C1103.2 C1104.2 C1139.2 C1140.2 C1141.2 C1142.2 C1143.1 C1144.1 C1145.1 C1146.1 C1147.1 C1148.1 C1149.1 C1150.2 C1151.2 C1152.2 C1153.2 C1154.2 C1155.2 C1156.2 C1157.2 C1174.2 C1253.2 C1255.2 C1256.2 C1258.2 C1259.2 C1271.2 C1272.2 C1273.2 C1274.2 C1275.2 C1276.2 C1277.2 C1278.2 C1282.2 C1283.2 C1305.2 C1434.2 C1435.2 C1436.2 C1437.2 C1438.2 C1439.2 C1440.2 C1441.2 C1442.2 C1443.2 C1444.2 C1445.2 C1446.2 C1447.2 C1448.2 C1449.2 C1450.2 C1451.2 C1452.2 C1453.2 C1454.2 C1455.2 C1456.2 C1457.2 C1458.2 C1459.2 FL18.2(GND) FL19.2(GND) FL22.2(GND) FL28.2(GND) FL29.2(GND) FL30.2(GND) J46.1(GND1) J46.7(GND2) J46.18(GND3) J46.33(GND5) J46.39(GND4) J46.45(GND6) J46.51(GND7) J46.57(GND8) J46.63(GND9) J46.69(GND10) J46.75(GND11) J52.1(GND1) J52.7(GND2) J52.18(GND3) J52.33(GND5) J52.39(GND4) J52.45(GND6) J52.51(GND7) J52.57(GND8) J52.63(GND9) J52.69(GND10) J52.75(GND11) J63.2 J64.2 J65.2 P1.1(GND2) P1.20(GND1) P2.1(GND2) P2.20(GND1) R33.2 R36.2 R202.2 R277.1 R652.1 R653.1 R655.2 R661.2 R662.2 R745.2 R775.1 R776.1 R945.1 U14.AG6(SD1_RX0_P) U14.AG8(SD1_RX1_P) U14.AG11(SD1_RX3_P) U14.AG13(SD1_REF_CLK1_P) U14.AG15(SD2_RX0_P) U14.AG18(SD2_RX2_P) U14.AH6(SD1_RX0_N) U14.AH8(SD1_RX1_N) U14.AH11(SD1_RX3_N) U14.AH13(SD1_REF_CLK1_N) U14.AH15(SD2_RX0_N) U14.AH18(SD2_RX2_N) U24.2(GND) U28.5(GND) U50.41(EPAD) U123.139(VSS_CASE) U123.D9(VSS/EFUSE) U523.2(SDI) U523.8(VSS) U524.1(NC) U524.3(A2) U524.4(VSS) U525.8(VSS) U527.3(GND) U538.4(GND) ; also on sheet 5 6 7 8 9 10 11 12 17 18 19 20
GND_EARTH: C386.1 C388.1 P1.S1(CHASSIS_GND1) P1.S2(CHASSIS_GND2) P1.S3(CHASSIS_GND3) P1.S4(CHASSIS_GND4) P2.S1(CHASSIS_GND1) P2.S2(CHASSIS_GND2) P2.S3(CHASSIS_GND3) P2.S4(CHASSIS_GND4) R202.1 ; also on sheet 5 17 19 20
VBAT: BT3.1(pos1) BT3.2(pos2) C1253.1 U523.19(VBAT)
VDD_CLKOUT: C1436.1 C1437.1 C1438.1 C1439.1 C1440.1 C1441.1 C1442.1 FL30.1(IN_OUT) U50.15(VDDO0) U50.18(VDDO1) U50.25(VDDO2) U50.28(VDDO3) U50.33(VDDO4)
VDD_LP: R144.1 ; also on sheet 8 17
VDD_Si5332: C1273.1 C1274.1 C1275.1 C1276.1 C1277.1 FL28.1(IN_OUT) U50.1(VDD_DIG) U50.4(VDD_XTAL) U50.9(VDDA)
VDDO7: C1278.1 FL29.1(IN_OUT) U50.40(VDDO5)
32KHZ_LP_RTC: R25.2 R33.1 U24.3(2A)
32KHZ_RTC: R36.1 R953.2 U24.1(1A)
BUFF_I2C1_SCL: J65.3 R856.2 U538.2(SCLOUT)
BUFF_I2C1_SDA: J65.1 R855.2 U538.7(SDAOUT)
CLK_32KHZ: R25.1 R739.2 R953.1 U523.7(CLKOUT)
CLK_RTC: R143.2 U24.6(1Y) ; also on sheet 17
CLKGEN_OUT2_N: R792.1 U50.21(OUT2B)
CLKGEN_OUT2_P: R791.1 U50.22(OUT2)
CLKGEN_OUT3_N: R788.1 U50.23(OUT3B)
CLKGEN_OUT3_P: R787.1 U50.24(OUT3)
CLKGEN_OUT4_N: R790.1 U50.26(OUT4B)
CLKGEN_OUT4_P: R789.1 U50.27(OUT4)
CLKGEN_OUT5_N: R786.1 U50.29(OUT5B)
CLKGEN_OUT5_P: R785.1 U50.30(OUT5)
CLKGEN_OUT6_N: R784.1 U50.34(OUT6B)
CLKGEN_OUT6_P: R783.1 U50.35(OUT6)
CLKGEN_OUT7: R781.1 U50.39(OUT7)
CLKGEN_OUT8: R782.1 U50.38(OUT7B)
CPU_SVDD: R260.2 R261.2 ; also on sheet 9
CPU_XVDD: R258.2 R259.2 ; also on sheet 9
DDR_CLK_100MHZ_LVCMOS : R782.2 ; also on sheet 17
DIFF_SYSCLK_N: U50.16(OUT1B) ; also on sheet 17
DIFF_SYSCLK_P: U50.17(OUT1) ; also on sheet 17
EMI2_MDC: U123.C11(MDC) ; also on sheet 18
EMI2_MDIO: U123.D10(MDIO) ; also on sheet 18
I2C1_CH0_SCL: R750.2 U28.8(SCLK) U523.1(SCL) U524.6(SCL) U525.5(SC0) ; also on sheet 6 7
I2C1_CH0_SDA: R751.2 U28.7(SDATA) U523.4(SDA/~{CE}) U524.5(SDA) U525.4(SD0) ; also on sheet 6 7
I2C1_M2CARD1_SCL: J46.60(I2C_CLK) R756.2 U525.7(SC1)
I2C1_M2CARD1_SDA: J46.58(I2C_DATA) R757.2 U525.6(SD1)
I2C1_M2CARD2_SCL: J52.60(I2C_CLK) R754.2 U525.10(SC2)
I2C1_M2CARD2_SDA: J52.58(I2C_DATA) R755.2 U525.9(SD2)
I2C1_SCL: R749.2 U525.14(SCL) U538.3(SCLIN) ; also on sheet 17
I2C1_SDA: R748.2 U525.15(SDA) U538.6(SDAIN) ; also on sheet 17
I2C1_uBUS_SCL: R752.2 U525.12(SC3) ; also on sheet 19
I2C1_uBUS_SDA: R753.2 U525.11(SD3) ; also on sheet 19
I2C3_SCL: J64.3 R854.2 ; also on sheet 17
I2C3_SDA: J64.1 R853.2 ; also on sheet 17
I2C4_SCL: J63.3 R852.2 ; also on sheet 17
I2C4_SDA: J63.1 R851.2 ; also on sheet 17
I2C_ADDR_A0: R277.2 U50.10(INPUT1)
IRQ_RTC_B: R742.1 U523.17(~{INT}) ; also on sheet 17
M2_1_REFCLK_EN#: R775.2 R798.1 U50.19(INPUT2)
M2_1_REFCLK_N: J46.49(REFCLK_N0) R788.2
M2_1_REFCLK_P: J46.47(REFCLK_P0) R787.2
M2_2_REFCLK_EN#: R776.2 R806.1 U50.20(INPUT3)
M2_2_REFCLK_N: J52.49(REFCLK_N0) R786.2
M2_2_REFCLK_P: J52.47(REFCLK_P0) R785.2
OUT6_OE_B: R945.2 R946.2 U50.31(INPUT4)
OVDD: FL29.3(OUT_IN) R143.1 R656.1 U527.5(VCC) ; also on sheet 6 9 12 17 18 19
PEXM2_1_COEX1: J46.48(COEX1) TP130.1(Pin1)
PEXM2_1_COEX2: J46.46(COEX2) TP129.1(Pin1)
PEXM2_1_COEX3: J46.44(COEX3) TP128.1(Pin1)
PEXM2_2_COEX1: J52.48(COEX1) TP141.1(Pin1)
PEXM2_2_COEX2: J52.46(COEX2) TP140.1(Pin1)
PEXM2_2_COEX3: J52.44(COEX3) TP139.1(Pin1)
PEXM2_CLKREQ: J46.53(~{CLKREQ0}) R668.2 R798.2
PEXM2_CLKREQ2: J52.53(~{CLKREQ0}) R805.2 R806.2
PEXM2_LED1: D510.C(CATHODE) J46.6(~{LED1})
PEXM2_LED2: D511.C(CATHODE) J52.6(~{LED1})
PEXM2_PET1_N: C1168.1 J46.37(PET_N0)
PEXM2_PET1_P: C1166.1 J46.35(PET_P0)
PEXM2_PET2_N: C1294.1 J52.37(PET_N0)
PEXM2_PET2_P: C1293.1 J52.35(PET_P0)
PEXM2_WAKE2_B: J52.55(~{PEWAKE0}) R804.2
PEXM2_WAKE_B: J46.55(~{PEWAKE0}) R667.2
PORESET_B: U527.2(A) ; also on sheet 12 18
QSG0_LED0: R645.1 U123.E2(LED0_PHY0)
QSG0_LED1: R646.1 U123.D1(LED1_PHY0)
QSG0_MDI0_N: P1.21(TRD1-) U123.D30(P0_D0N)
QSG0_MDI0_P: P1.15(TRD1+) U123.D31(P0_D0P)
QSG0_MDI1_N: P1.16(TRD2-) U123.C24(P0_D1N)
QSG0_MDI1_P: P1.23(TRD2+) U123.C25(P0_D1P)
QSG0_MDI2_N: P1.24(TRD3-) U123.C23(P0_D2N)
QSG0_MDI2_P: P1.18(TRD3+) U123.D29(P0_D2P)
QSG0_MDI3_N: P1.19(TRD4-) U123.C21(P0_D3N)
QSG0_MDI3_P: P1.26(TRD4+) U123.C22(P0_D3P)
QSG1_LED0: R643.1 U123.C3(LED0_PHY1)
QSG1_LED1: R644.1 U123.B2(LED1_PHY1)
QSG1_MDI0_N: P1.13(TRD1-) U123.B17(P1_D0N)
QSG1_MDI0_P: P1.6(TRD1+) U123.B18(P1_D0P)
QSG1_MDI1_N: P1.5(TRD2-) U123.C28(P1_D1N)
QSG1_MDI1_P: P1.11(TRD2+) U123.C29(P1_D1P)
QSG1_MDI2_N: P1.10(TRD3-) U123.B15(P1_D2N)
QSG1_MDI2_P: P1.3(TRD3+) U123.B16(P1_D2P)
QSG1_MDI3_N: P1.2(TRD4-) U123.C26(P1_D3N)
QSG1_MDI3_P: P1.8(TRD4+) U123.C27(P1_D3P)
QSG2_LED0: R647.1 U123.C5(LED0_PHY2)
QSG2_LED1: R648.1 U123.D5(LED1_PHY2)
QSG2_MDI0_N: P2.21(TRD1-) U123.C32(P2_D0N)
QSG2_MDI0_P: P2.15(TRD1+) U123.C33(P2_D0P)
QSG2_MDI1_N: P2.16(TRD2-) U123.B19(P2_D1N)
QSG2_MDI1_P: P2.23(TRD2+) U123.B20(P2_D1P)
QSG2_MDI2_N: P2.24(TRD3-) U123.A9(P2_D2N)
QSG2_MDI2_P: P2.18(TRD3+) U123.A10(P2_D2P)
QSG2_MDI3_N: P2.19(TRD4-) U123.C30(P2_D3N)
QSG2_MDI3_P: P2.26(TRD4+) U123.C31(P2_D3P)
QSG3_LED0: R649.1 U123.B4(LED0_PHY3)
QSG3_LED1: R650.1 U123.C6(LED1_PHY3)
QSG3_MDI0_N: P2.13(TRD1-) U123.C36(P3_D0N)
QSG3_MDI0_P: P2.6(TRD1+) U123.C1(P3_D0P)
QSG3_MDI1_N: P2.5(TRD2-) U123.D34(P3_D1N)
QSG3_MDI1_P: P2.11(TRD2+) U123.D35(P3_D1P)
QSG3_MDI2_N: P2.10(TRD3-) U123.C34(P3_D2N)
QSG3_MDI2_P: P2.3(TRD3+) U123.C35(P3_D2P)
QSG3_MDI3_N: P2.2(TRD4-) U123.D32(P3_D3N)
QSG3_MDI3_P: P2.8(TRD4+) U123.D33(P3_D3P)
QSGM_REXT: R662.1 U123.A8(REF_REXT)
QSGM_REXT0: R663.1 U123.D17(SERDES_REXT_0)
QSGM_REXT1: R663.2 U123.D18(SERDES_REXT_1)
QSGPHY1_INT_B: R656.2 R660.2 ; also on sheet 17
QSGPHY1_RST_B: R654.1 U123.B5(NRESET) ; also on sheet 18
QSGPHY_REFCLK_125M_N: C850.1 U50.13(OUT0B)
QSGPHY_REFCLK_125M_P: C849.1 U50.14(OUT0)
RST_I2CMUX_B: R758.2 U525.3(~{RESET}) U527.4(Y)
SD1_IMP_CAL_RX: R260.1 U14.Y11(SD1_IMP_CAL_RX)
SD1_IMP_CAL_TX: R258.1 U14.AA6(SD1_IMP_CAL_TX)
SD1_REFCLK2_N: R792.2 U14.AB8(SD1_REF_CLK2_N)
SD1_REFCLK2_P: R791.2 U14.AA8(SD1_REF_CLK2_P)
SD1_RX2_N: C1583.1 U123.D13(RDN_0)
SD1_RX2_P: C1582.1 U123.D14(RDP_0)
SD1_TX2_N: C848.1 U14.AE10(SD1_TX2_N)
SD1_TX2_P: C847.1 U14.AD10(SD1_TX2_P)
SD2_IMP_CAL_RX: R261.1 U14.Y12(SD2_IMP_CAL_RX)
SD2_IMP_CAL_TX: R259.1 U14.Y20(SD2_IMP_CAL_TX)
SD2_REFCLK1_N: R784.2 U14.AE13(SD2_REF_CLK1_N)
SD2_REFCLK1_P: R783.2 U14.AD13(SD2_REF_CLK1_P)
SD2_REFCLK2_N: R790.2 U14.AB19(SD2_REF_CLK2_N)
SD2_REFCLK2_P: R789.2 U14.AB18(SD2_REF_CLK2_P)
SD2_RX1_N: J46.43(PER_N0) U14.AH16(SD2_RX1_N)
SD2_RX1_P: J46.41(PER_P0) U14.AG16(SD2_RX1_P)
SD2_RX3_N: J52.43(PER_N0) U14.AH19(SD2_RX3_N)
SD2_RX3_P: J52.41(PER_P0) U14.AG19(SD2_RX3_P)
SD2_TX1_N: C1168.2 U14.AE16(SD2_TX1_N)
SD2_TX1_P: C1166.2 U14.AD16(SD2_TX1_P)
SD2_TX3_N: C1294.2 U14.AE19(SD2_TX3_N)
SD2_TX3_P: C1293.2 U14.AD19(SD2_TX3_P)
Si5332_SCL: R777.2 U50.11(SCLK)
Si5332_SDA: R778.2 U50.12(SDA)
SLOT1_RST_B: J46.52(~{PERST0}) R666.2 ; also on sheet 18
SLOT2_RST_B: J52.52(~{PERST0}) R803.2 ; also on sheet 18
SYS_CLK_100MHz_LVCMOS: R781.2 ; also on sheet 17
TA_BB_RTC: R144.2 U24.4(2Y) ; also on sheet 8
TDI_ANODE: C437.2 U28.2(D_PLUS) ; also on sheet 17
TDI_CATHODE: C437.1 U28.3(D_MINUS) ; also on sheet 17
THERM_FAULT_B: R743.1 U28.4(~{T_CRIT}) ; also on sheet 17
THERM_WARN_B: R744.1 U28.6(~{ALERT}) ; also on sheet 17
U25_IFS: U523.5(IFS) U523.18(BBS)
N26564824: C847.2 U123.D16(TDP_0)
N26564835: C848.2 U123.D15(TDN_0)
N26564871: C849.2 U123.D11(REFCLK_P)
N26564875: C850.2 U123.D12(REFCLK_N)
N26565200: R651.2 R653.2 U123.B7(REFCLK_SEL1)
N26565210: R652.2 U123.B8(REFCLK_SEL0)
N26565245: R655.1 U123.D8(COMA_MODE)
N26565259: R661.1 U123.C7(JTAG_TRST)
N26565267: C693.1 U123.A7(REF_FILT)
N26565570: R660.1 U123.C10(MDINT)
N26565580: R657.1 U123.C19(PHYADD2)
N26565586: R658.1 U123.B12(PHYADD3)
N26565592: R659.1 U123.D26(PHYADD4)
N26602439: C772.1 P1.7(TRCT1)
N26602442: C1021.1 P1.12(TRCT2)
N26602445: C1022.1 P1.4(TRCT3)
N26602448: C1023.1 P1.9(TRCT4)
N26631448: C1140.1 P1.31(LED3_C) R643.2
N26631451: C1139.1 P1.34(LED4_GA) R644.2
N26631860: C1142.1 P1.27(LED1_C) R645.2
N26631884: C1141.1 P1.30(LED2_GA) R646.2
N26633114: C1024.2 P1.14(TRCT1)
N26633139: C1143.2 P1.22(TRCT2)
N26633162: C1144.2 P1.17(TRCT3)
N26633185: C1145.2 P1.25(TRCT4)
N26633865: C1146.2 P2.14(TRCT1)
N26633881: C1147.2 P2.22(TRCT2)
N26633897: C1148.2 P2.17(TRCT3)
N26633913: C1149.2 P2.25(TRCT4)
N26633941: C1150.1 P2.27(LED1_C) R647.2
N26633965: C1151.1 P2.30(LED2_GA) R648.2
N26634920: C1152.1 P2.7(TRCT1)
N26634936: C1153.1 P2.12(TRCT2)
N26634952: C1154.1 P2.4(TRCT3)
N26634968: C1155.1 P2.9(TRCT4)
N26634994: C1157.1 P2.31(LED3_C) R649.2
N26635018: C1156.1 P2.34(LED4_GA) R650.2
N26645840: J46.56(~{W_DISABLE1}) R669.1
N26649122: D510.A(ANODE) R922.1
N26756957: TP127.1(Pin1) U523.6(~{TS})
N26760872: R745.1 U524.7(WP)
N26860199: J52.56(~{W_DISABLE1}) R801.1
N26860244: D511.A(ANODE) R923.1
N26937676: R857.2 U538.1(EN)
N26937874: R858.1 U538.5(READY)
N29074387: C1582.2 U14.AG10(SD1_RX2_P)
N29074390: C1583.2 U14.AH10(SD1_RX2_N)

Not connected (* = marked no-connect by the designer): J46 3(USB_D+)* 5(USB_D-)* 8(I2S_SCK)* 9(SDIO_CLK)* 10(I2S_WS)* 11(SDIO_CMD)* 12(I2S_SD_IN)* 13(SDIO_DATA0)* 14(I2S_SD_OUT)* 15(SDIO_DATA1)* 16(~{LED2})* 17(SDIO_DATA2)* 19(SDIO_DATA3)* 20(~{UART_WAKE})* 21(~{SDIO_WAKE})* 22(UART_RXD)* 23(~{SDIO_RST})* 32(UART_TXD)* 34(UART_CTS)* 36(UART_RTS)* 38(VEN_DEF1)* 40(VEN_DEF2)* 42(VEN_DEF3)* 50(SUSCLK)* 54(~{W_DISABLE2})* 59(PET_P1)* 61(PET_N1)* 62(~{ALERT})* 64(RESERVED) 65(PER_P1)* 66(~{PERST1})* 67(PER_N1)* 68(~{CLKREQ1})* 70(~{PEWAKE1})* 71(REFCLK_P1)* 73(REFCLK_N1)*; J52 3(USB_D+)* 5(USB_D-)* 8(I2S_SCK)* 9(SDIO_CLK)* 10(I2S_WS)* 11(SDIO_CMD)* 12(I2S_SD_IN)* 13(SDIO_DATA0)* 14(I2S_SD_OUT)* 15(SDIO_DATA1)* 16(~{LED2})* 17(SDIO_DATA2)* 19(SDIO_DATA3)* 20(~{UART_WAKE})* 21(~{SDIO_WAKE})* 22(UART_RXD)* 23(~{SDIO_RST})* 32(UART_TXD)* 34(UART_CTS)* 36(UART_RTS)* 38(VEN_DEF1)* 40(VEN_DEF2)* 42(VEN_DEF3)* 50(SUSCLK)* 54(~{W_DISABLE2})* 59(PET_P1)* 61(PET_N1)* 62(~{ALERT})* 64(RESERVED)* 65(PER_P1)* 66(~{PERST1})* 67(PER_N1)* 68(~{CLKREQ1})* 70(~{PEWAKE1})* 71(REFCLK_P1)* 73(REFCLK_N1)*; U14 AA20(SD2_PLL2_TPD)* AB5(SD1_PLL2_TPD)* AC13(SD2_PLL1_TPD)* AD6(SD1_TX0_P)* AD8(SD1_TX1_P)* AD11(SD1_TX3_P)* AD15(SD2_TX0_P)* AD18(SD2_TX2_P)* AE6(SD1_TX0_N)* AE8(SD1_TX1_N)* AE11(SD1_TX3_N)* AE15(SD2_TX0_N)* AE18(SD2_TX2_N)* AF5(SD1_PLL2_TPA)* AF12(SD1_PLL1_TPA)* AF13(SD1_PLL1_TPD)* AF14(SD2_PLL1_TPA)* AF20(SD2_PLL2_TPA)*; U50 2(CLKIN)* 3(CLKIN_2B)* 5(NC1)* 6(NC2)* 7(CLKIN_3)* 8(CLKIN_3B)* 32(INPUT5)* 36(INPUT6)* 37(INPUT7)*; U123 A1(NC)* A2(LED2_PHY3)* A3(JTAG_TMS)* A4(NC)* A5(NC)* A6(NC)* B1(THERMDA)* B3(LED2_PHY2)* B6(JTAG_CLK)* B9(GPIO4)* B10(GPIO7)* B11(GPIO13)* B13(RESERVED_5)* B14(RESERVED_4)* C2(LED3_PHY0)* C4(LED2_PHY1)* C8(JTAG_DO)* C9(JTAG_DI)* C12(RESERVED_1)* C13(RESERVED_2)* C14(GPIO1)* C15(GPIO3)* C16(GPIO5)* C17(GPIO8)* C18(GPIO12)* C20(RESERVED_6)* D2(LED2_PHY0)* D3(THERMDC_VSS)* D4(LED3_PHY1)* D6(LED3_PHY2)* D7(LED3_PHY3)* D19(GPIO0)* D20(GPIO2)* D21(GPIO6)* D22(GPIO9)* D23(GPIO11)* D24(GPIO10)* D25(GPIO14)* D27(RESERVED_7)* D28(RESERVED_3)*; U523 3(SDO)* 9(NC1)* 10(NC2)* 11(NC3)* 12(NC4)* 13(NC5)* 14(NC6)* 15(NC7)* 16(NC8)*; U527 1(NC)*

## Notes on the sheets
sheet 13
- SERDES INTERFACE
- If the SerDes interface is entirely
  or partly unused, the unused pins
  must be pulled down to SD_GND.
- To M.2_SLOT1
- To M.2_SLOT1
- To F104S8A
- To F104S8A
- To M.2_SLOT2
- To M.2_SLOT2
- If the SerDes lanes are unused,
  pull it down to SD_GND.
- Required In case of PCIe Gen 3  M2 card
- Lane0: Unused
  Lane1: Unused
  Lane2: QSGMII [Both LS1046 & 43 ]
  Lane3: Unused
- Lane0: Unused
  Lane1: PCIe#2x1 [Both LS1046 & 43 ]
  Lane2: Unused
  Lane3: PCIe#3x1 [Both LS1046 & 43 ]
- CLOCK GENERATOR
- 125 MHz (LVDS33)
- Outputs:
     OUT0: 125 MHz LVDS Fast 3.3 V
     OUT1: 100 MHz LVDS Fast 3.3 V
     OUT2: 100 MHz HCSL 3.3 V 50 Ohms - Internal Termination
     OUT3: 100 MHz HCSL 3.3 V 50 Ohms - Internal Termination
           OEB INPUT2 (P19)
     OUT4: 100 MHz HCSL 3.3 V 50 Ohms - InternalTermination
     OUT5: 100 MHz HCSL 3.3 V 50 Ohms - InternalTermination
           OEB INPUT3 (P20)
     OUT6: 100 MHz HCSL 3.3 V 50 Ohms - Internal Termination
           OEB INPUT4 (P31)
     OUT7: 100 MHz LVCMOS (in-phase) 1.8 V 50 Ohms
- 100 MHz (LVDS33)
- 100 MHz (HCSL33)
- 100 MHz (HCSL33)
- 100 MHz (HCSL33)
- 100 MHz (HCSL33)
- 1.8V LVCMOS [In Phase]
- 1.8V LVCMOS [In Phase]
- 7-Bit Address = 0x6A
sheet 14
- M.2 Connector (I)
  Only for PEX WiFi (Type E) Supports 1630 and 2230 modules only
- 3.3V
- Mounting Hole for M.2 Slots
- i
- NOTE:
- ONLY  1630 anf 2230 Size M.2 Type E  modules shal be supported.
- Near J52 and J46 at 30mm
  (Shouldered STANDOFF M2X0.4 SMD]
- M.2 Connector (2)
  Only for PEX WiFi (Type E) Supports 1630 and 2230 modules only
- 3.3V
- i
- NOTE:
- ONLY  1630 anf 2230 Size M.2 Type E  modules shal be supported.
sheet 15
- QSGMII PHY INTERFACE
- PORT1
- PORT2
- PORT3
- PORT4
- REFCLK_SEL[1:0] = 00
  for 125MHz clock
- PHY ADDR = 0x1C - 0x1F
- Join as single point then to
  analog ground plane
sheet 16
- I2C MUX
- I2C INTERFACE
- System RTC
- Thermal
  Monitor
- EEPROM
- 7-Bit Address = 0x4C
- 7-Bit Address = 0x77
- I2C1 ADDRESS:
  52H & 53H
- 7-Bit Address = 0x51
- CLK_32KHZ_ BUFFER
- I2C EXPANSION HEADERS
- I2C3
- I2C1
- I2C4
